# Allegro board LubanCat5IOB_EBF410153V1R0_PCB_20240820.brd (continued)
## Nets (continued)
N16593791: R12.2 R13.1 R17.1 U2.11(FB)
N16594273: J5.1 J5.5 L1.1
N16594503: C26.1 R9.2 R16.1 U2.12(EN)
N16594633: R15.2 U2.3(PG)
N16594645: R14.2 R18.1 U2.6(MODE)
N16594663: C25.1 R14.1 R15.1 U2.9(VCC)
N16594691: R8.1 U2.8(BST)
N16605614: C36.1 J6.15(SH) J6.16(SH1) R42.1
N16605678: J6.13(YELC) R39.1
N16605786: R45.1 U4.32(LED0)
N16605856: C35.1 J6.1(CT)
N16606070: J6.12(GRLC) R40.1
N16606404: L4.1 U4.30(REG_OUT)
N16606548: R25.1 U4.39(RSET)
N16607242: R23.2 U4.25(RXD0)
N16607246: R24.2 U4.24(RXD1)
N16607250: R26.2 U4.23(RXD2)
N16607260: R27.2 U4.22(RXD3)
N16607264: R28.2 U4.27(RXC)
N16607268: R29.2 U4.26(RXCTL)
N16607434: C33.1 R384.1 Y1.1
N16607930: R35.2 U4.31(INTB)
N16608272: C34.1 R385.2 U4.36(XTAL_IN) Y1.3
N16611232: C58.1 D7.2 R69.2 R70.2 U3.12(PHYRSTB)
N16611438: C57.1 J7.15(SH) J7.16(SH1) R71.1
N16611542: R74.1 U3.32(LED0)
N16611608: C56.1 J7.1(CT)
N16612146: L7.1 U3.30(REG_OUT)
N16612282: R53.1 U3.39(RSET)
N16612988: R51.2 U3.25(RXD0)
N16612992: R52.2 U3.24(RXD1)
N16612996: R54.2 U3.23(RXD2)
N16613006: R55.2 U3.22(RXD3)
N16613010: R56.2 U3.27(RXC)
N16613014: R57.2 U3.26(RXCTL)
N16613204: C54.1 R387.1 Y2.1
N16613212: C55.1 R386.2 U3.36(XTAL_IN) Y2.3
N16613364: J7.11(GRLA) R64.1
N16613452: J7.13(YELC) R66.1
N16613812: R63.2 U3.31(INTB)
N16620498: R95.1 U6.3(ISET)
N16620622: C86.1 R93.2 U6.4(EN)
N16621700: J8.1(SH1) J8.2(SH2) J8.3(SH3) J8.4(SH4) L12.1
N16621974: R106.1 U14.15(DPU)
N16621978: R107.1 U14.14(DMU)
N16622106: J10.5(SH1) J10.6(SH2) J10.11(SH1) J10.12(SH2) L13.1
N16622154: C104.1 C105.1 R111.1 U15.2(VCC)
N16622302: R109.2 R110.2 U15.3(OUT)
N16622762: J9.19(SH1) J9.20(SH2) J9.21(SH1) J9.22(SH2) L11.1
N16624042: R103.1 U13.3(ISET)
N16624166: C99.1 R102.2 U13.4(EN)
N16624284: R99.1 U7.3(ISET)
N16624408: C89.1 R96.2 U7.4(EN)
N16625162: C102.1 U14.3(XOUT) Y3.1
N16625190: C103.1 U14.4(XIN) Y3.3
N16625358: R108.1 U14.13(REXT)
N16625468: C98.1 R101.1 U14.17(VBUSM)
N16625496: R105.1 U14.16(XRSTJ)
N16625548: R104.1 U14.18(BUSJ)
N16630017: R121.2 U16.26(CE)
N16630071: C106.1 C107.1 R112.1 U16.17(AVDD)
N16630361: C112.1 U16.24(LIN1)
N16630365: C113.1 U16.23(RIN1)
N16630441: C115.1 U16.22(LIN2)
N16630445: C117.1 U16.21(RIN2)
N16630545: C118.1 U16.20(VMID)
N16630549: C119.1 U16.19(ADCVREF)
N16630553: C120.1 U16.10(VREF)
N16778766: Q10.1(GATE) Q11.1(GATE) Q12.1(GATE) Q13.1(GATE) R169.2 R171.1
N16778768: Q12.3(DRAIN) R165.2 R166.2
N16778770: Q13.3(DRAIN) R167.2 R168.2
N16778784: J16.G1(20) J16.G2(21) J16.G3(22) J16.G4(23) R156.1
N16779726: Q8.1(GATE) Q9.3(DRAIN) R158.2
N16779736: Q9.1(GATE) R159.1 R160.1
N16779830: Q10.3(DRAIN) R161.2 R162.2
N16779838: Q11.3(DRAIN) R163.2 R164.2
N16779929: C142.1 Q7.1(GATE) R153.2
N16781420: Q19.1(GATE) Q20.1(GATE) Q21.1(GATE) Q22.1(GATE) R190.2 R192.1
N16781422: Q21.3(DRAIN) R186.2 R187.2
N16781424: Q22.3(DRAIN) R188.2 R189.2
N16781438: J17.G1(20) J17.G2(21) J17.G3(22) J17.G4(23) R177.1
N16782370: Q17.1(GATE) Q18.3(DRAIN) R179.2
N16782390: Q18.1(GATE) R180.1 R181.1
N16782474: Q19.3(DRAIN) R182.2 R183.2
N16782482: Q20.3(DRAIN) R184.2 R185.2
N16782583: C154.1 Q16.1(GATE) R174.2
N16783799: J18.G1(20) J18.G2(21) J18.G3(22) J18.G4(23) R195.1
N16783872: D40.1 R197.1 R200.1
N16786078: D46.1 R209.1
N16791174: Q28.1(BASE) R211.1 R212.2
N16794123: Q27.1(GATE) R213.2 R215.1
N16794280: Q27.3(DRAIN) R214.1
N16795019: C316.1 Q29.1(BASE) R193.2 R194.1
N16796110: Q28.3(COLLECTOR) R215.2
N16803397: C156.1 U25.6(BOOT)
N16803401: C156.2 L16.1 U25.2(SW)
N16803409: C157.1 R218.1 R227.1 U25.4(FB)
N16803499: R221.1 R222.1 U25.5(EN)
N16803635: C164.1 U26.5(X1) Y4.1
N16803642: R234.1 U26.10(IREF)
N16803673: C166.1 C167.1 R235.2 U26.15(VDDODA)
N16803735: R216.1 U26.20(CLK0P)
N16803772: R217.1 U26.19(CLK0N)
N16803867: R228.1 U26.18(CLK1P)
N16803869: R229.1 U26.17(CLK1N)
N16803965: C165.1 R230.1 Y4.3
N16804075: R230.2 U26.6(X2)
N16804652: J19.38(DEVSLP) R237.1
N16804754: J19.10(DAS/DSS) R236.1
N16810459: R238.1 U26.14(CLK2P)
N16810480: R239.1 U26.13(CLK2N)
N16810864: R242.1 U26.12(CLK3P)
N16810873: R243.1 U26.11(CLK3N)
N16814949: C188.1 U27.4(NC)
N16815530: R246.1 U27.3(EN)
N16823880: J20.B11(WAKE#) R247.2
N16823920: J20.B12(RSVD_B12) R248.2
N16831021: Q30.1(GATE) Q31.3(COLLECTOR) R255.2
N16831025: Q31.1(BASE) R256.2 R257.1
N16835418: C194.1 R249.1 R250.1 U28.4(FB)
N16835425: C179.2 L17.1 U28.2(SW)
N16835491: C179.1 U28.6(BOOT)
N16835549: R251.1 R252.1 U28.5(EN)
N16843509: C199.1 L18.1 U29.2(SW)
N16843563: R262.2 R263.1 U29.5(EN)
N16843694: C209.1 J21.2(RST) R258.2 U30.4
N16843698: C208.1 J21.3(CLK) R259.2 U30.5
N16843753: C200.2 R254.2 R261.1 U29.4(FB)
N16843960: J23.1(MIC-P) R264.2 R265.2
N16843974: J23.7(SPK-N) R266.2
N16843993: C199.2 U29.6(BOOT)
N16844137: J23.20(W-DISABLE) R267.1
N16844170: C207.1 J21.7(I/O) R253.2 R260.2 U30.1
N16844211: J23.22(PERST1) R268.1
N16844471: J23.38(USB-D+) R270.1
N16844509: J23.36(USB-D-) R269.1
N16890924: R65.1 U31.5(EN)
N16890968: C224.1 U31.6(BOOT)
N16890980: C224.2 L20.1 U31.2(SW)
N16890990: C225.1 R36.1 R271.1 U31.4(FB)
N16891594: R6.1 U1.5(EN)
N16891638: C6.1 U1.6(BOOT)
N16891644: C6.2 L2.1 U1.2(SW)
N16891660: C7.1 R4.1 R7.1 U1.4(FB)
N16892291: C14.2 L21.1 U32.2(SW)
N16892293: C232.1 R272.1 R274.1 U32.4(FB)
N16892339: C14.1 U32.6(BOOT)
N16892349: C239.1 R273.1 U32.5(EN)
N16906360: C241.1 U35.2(OSCO) Y5.2
N16906384: C240.1 U35.1(OSCI) Y5.1
N16906410: R276.2 R277.1 U35.7(CLKOUT)
N16921467: D58.1 R287.2
N16921931: D60.1 R293.2
N16922864: C247.1 U38.3(C1-)
N16922866: C247.2 U38.1(C1+)
N16922868: C248.1 U38.5(C2-)
N16922870: C248.2 U38.4(C2+)
N16922872: C246.1 U38.6(V-)
N16922874: C245.1 U38.2(V+)
N16935603: C128.1 R138.1 R141.1 U17.4(FB)
N16935613: C127.2 L25.1 U17.2(SW)
N16935675: C127.1 U17.6(BOOT)
N16935717: R139.1 R140.1 U17.5(EN)
N16966626: C259.1 C262.1 R306.2 U39.4(EN) U40.4(EN)
N16966707: C258.1 C265.1 R305.2 U18.4(EN) U41.4(EN)
N16966725: R307.1 U18.3(ISET)
N16966842: R310.1 U41.3(ISET)
N16967089: R308.1 U39.3(ISET)
N16967190: R309.1 U40.3(ISET)
N17015969: R323.1 U48.3(ISET)
N17016021: C284.1 R324.2 U48.4(EN)
N17044511: J13.55(PEWAKE0#) R147.2 R148.2
N17044551: J13.53(CLKREQ0#) R145.2
N17044654: J13.52(PERST0#) R144.1
N17044656: J13.56(W_DISABLE1#) R146.1
N17044766: J13.3(USB_D+) R142.2
N17044768: J13.5(USB_D-) R143.2
N17083881: Q5.1(GATE) Q32.3(COLLECTOR) R319.2
N17083895: Q32.1(BASE) R320.2 R321.1
N17085595: C290.1 R316.1 R322.1 U43.4(FB)
N17085599: C283.2 L26.1 U43.2(SW)
N17085653: C283.1 U43.6(BOOT)
N17085706: R317.1 R318.1 U43.5(EN)
N17139366: Q1.1(GATE) Q2.3(COLLECTOR) R132.2
N17139370: Q2.1(BASE) R133.2 R135.1
N17139392: D15.1(K) J12.1 R129.2
N17139440: Q1.2(SOURCE) R127.2 R131.2 R132.1
N17139454: Q1.3(DRAIN) R129.1
N17140097: C126.1 D83.2 P1.1(OUT) R126.2 R130.1
N17140111: C126.2 D78.2 P1.2(GND) R134.1 R136.1
N17140177: C125.1 R125.2 R126.1
N17141731: C210.1 C211.1 C218.1 C219.1 C278.1 R341.2 R342.2 U42.6(VDD)
N17141824: C303.1 C304.1 C305.1 C306.1 C307.1 R347.2 R348.2 U46.6(VDD)
N17141906: R345.2 R346.1 U42.1(CTRL)
N17141982: R343.2 U42.4(INN)
N17142014: C279.2 R343.1
N17142016: R344.2 U42.3(INP)
N17142030: C299.2 R344.1
N17142049: L19.1 U42.5(VON)
N17142051: L27.1 U42.8(VOP)
N17142055: C302.1 U42.2(BYPASS)
N17142188: R351.2 R352.1 U46.1(CTRL)
N17142262: R349.2 U46.4(INN)
N17142284: R350.2 U46.3(INP)
N17142286: C308.2 R349.1
N17142298: C309.2 R350.1
N17142317: L28.1 U46.5(VON)
N17142331: L29.1 U46.8(VOP)
N17142348: C312.1 U46.2(BYPASS)
N17143919: C288.1 D81.2 J11.6 R119.2 R120.1
N17143960: J11.2 R327.1
N17143962: C116.1 D82.2 J11.1 R114.1 R115.2 R116.1
N17143973: C111.1 R113.1 R115.1
N17144006: D79.2 J11.4 Q3.2(SOURCE)
N17144062: C289.1 Q3.1(GATE) Q4.1(GATE) R326.1
N17144068: C287.2 R124.2
N17144070: C122.2 R122.2
N17144072: Q3.3(DRAIN) R122.1 R123.1
N17144086: Q4.3(DRAIN) R124.1 R325.1
N17144157: D80.2 J11.3 Q4.2(SOURCE)
N17145436: D25.1 J41.2 R338.2
N17145440: D47.1 J41.3 R339.2
N17145452: D48.1 J41.4 R340.2
N17149601: LED1.2(ANODE) R11.2
N17201409: R353.2 U44.21(A0)
N17255856: D49.1 R354.1
N17266822: Q35.1(BASE) R334.2 R335.1
N17266886: LED2.2(ANODE) R128.2
N17266888: LED2.1(CATHODE) Q35.3(COLLECTOR)
N17604055: R384.2 R385.1 U4.37(XTAL_OUT)
N17605387: R386.1 R387.2 U3.37(XTAL_OUT)

Pads without a net: J1 30; J2 14 16; J4 4 6 16 22 24 26 28 52; J9 14 15 17 18; J11 7 8; J13 6 8 9 10 11 12 13 14 15 16 17 19 20 21 22 23 32 34 36 38 40 42 44 46 48 50 54 58 59 60 61 62 64 65 66 67 68 70 71 73; J14 14; J15 14; J18 14; J19 5 6 7 8 11 13 17 19 20 22 23 24 25 26 28 30 32 34 36 40 42 44 46 48 56 58 67 68 69; J20 A5 A6 A7 A8 A19 A25 A26 A29 A30 A32 B5 B6 B9 B23 B24 B27 B28 B30; J21 4 6; J23 3 5 6 16 17 19 28 30 32 42 44 45 46 47 48 49 51; J28 1; J29 1; J32 13 14; J33 13 14; J34 13 14 16 17 19 20; J35 13 14 16 17 19 20; J36 13 14 16 17 19 20; J37 13 14 16 17 19 20; NOREF 1; NOREF#2 1; NOREF#3 1; NOREF#5 1; NOREF#7 1; NOREF#9 1; NOREF#10 1; NOREF#11 1; NOREF#12 1; NOREF#13 1; NOREF#14 1; NOREF#15 1; NOREF#16 1; NOREF#17 1; NOREF#18 1; NOREF#19 1; U2 4; U14 2 19 21 22 23 24; U16 9 25; U30 3; U44 1

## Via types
v1: diameter 0.406, hole 0.203, TOP to BOTTOM, 2357 vias
v2: diameter 0.356, hole 0.203, TOP to BOTTOM, 308 vias
v3: diameter 0.508, hole 0.254, TOP to BOTTOM, 4 vias

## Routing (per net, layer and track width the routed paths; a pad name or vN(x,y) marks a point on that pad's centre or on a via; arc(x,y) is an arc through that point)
1V05_AVDD_PHY0: length 18.4
  TOP w0.203: U4.3 v1(71.46,81.04) ; v1(74.47,79.22) 74.11,78.87 U4.38 ; U4.8 v1(69.46,81.04)
  TOP w0.254: R47.2 v1(77.47,75.33) C42.1
  ART04 w0.381: v1(69.46,81.04) v1(71.46,81.04) 71.88,80.62 71.88,79.6 72.26,79.22 v1(74.47,79.22) 77.13,79.22 77.47,78.88 v1(77.47,75.33)
  BOTTOM w0.254: C41.1 73.75,78.5 v1(74.47,79.22)
1V05_AVDD_PHY1: length 20.5
  TOP w0.203: U3.8 v1(51.06,81.04) ; v1(56.07,79.1) 55.94,79.1 55.71,78.87 U3.38 ; U3.3 v1(53.06,81.04)
  TOP w0.254: C65.1 v1(58.67,75.33) R76.2
  ART04 w0.381: 55.3,79.22 54.94,78.87 54.94,75.83 56.03,74.74 56.64,74.74 57.23,75.33 v1(58.67,75.33) ; 55.3,79.22 54.94,79.58 54.94,80.51 54.41,81.04 v1(53.06,81.04) ; 55.3,79.22 55.94,79.22 v1(56.07,79.1)
  BOTTOM w0.254: v1(51.06,81.04) 51.42,80.68 C62.1 C63.1 53.2,80.9 v1(53.06,81.04) ; C64.1 55.82,79.1 v1(56.07,79.1)
1V05_DVDD_PHY0: length 11.1
  TOP w0.203: U4.21 68.66,74.64 v1(68.53,74.51)
  TOP w0.254: R46.1 v1(76.45,75.33) C39.1
  ART04 w0.381: v1(76.45,75.33) 76.2,75.07 72.9,75.07 72.64,75.33 69.35,75.33 v1(68.53,74.51)
  BOTTOM w0.381: C38.1 68.55,74.54 v1(68.53,74.51)
1V05_DVDD_PHY1: length 20.9
  TOP w0.203: U3.21 50.26,74.74 v1(50.08,74.56)
  TOP w0.254: R75.1 v1(59.69,75.33) C60.1
  ART04 w0.381: v1(50.08,74.56) 51.18,74.56 52.83,72.91 57.4,72.91 58.17,73.67 61.98,73.67 62.48,74.18 62.48,75.45 61.98,75.96 60.33,75.96 v1(59.69,75.33)
  BOTTOM w0.381: v1(50.08,74.56) 50.15,74.64 C61.1
1V8_DVDD_PHY1: length 33
  TOP w0.178: v1(53.11,74.54) 53.06,74.59 U3.28
  TOP w0.254: R381.1 C59.1 v1(61.6,75.32)
  ART04 w0.381: v1(53.11,74.54) 53.95,73.7 56.54,73.7 57.28,74.44 60.72,74.44 v1(61.6,75.32)
  BOTTOM w0.254: v1(53.11,74.54) 52.91,74.34 50.9,74.34 50.42,73.85 R48.1 R49.1 ; R70.1 44.71,79.52 R62.1 R61.1 46.4,81.22 47.52,81.22 48.01,80.73 48.01,78.81 49.43,77.38 49.43,72.93 R49.1 ; R49.1 R50.1
  BOTTOM w0.381: v1(53.11,74.54) 53.2,74.63 C51.1 C50.1
3V3_AVDD_PHY0: length 18.6
  TOP w0.203: U4.40 73.26,79.67 73.47,79.87 v1(73.47,81.11) ; v1(66.92,80.37) 67.62,79.67 U4.11
  TOP w0.254: v1(73.47,81.11) 73.47,81.68 73.98,82.18 C45.1
  TOP w0.305: R364.1 77.25,82.79 75.92,82.79 75.45,82.32 C45.1
  BOTTOM w0.254: v1(66.92,80.37) 67.09,80.53 C46.1 67.67,81.8 68.18,82.31 72.96,82.31 73.47,81.8 v1(73.47,81.11) 73.63,80.95 C44.1
3V3_AVDD_PHY1: length 17.2
  TOP w0.203: v1(49.56,81.04) U3.11 ; v1(55.07,81.11) 55.07,79.87 54.86,79.67 U3.40
  TOP w0.254: R383.1 60.2,82.18 59.56,82.82 58.3,82.82 C67.1 55.58,82.18 55.07,81.68 v1(55.07,81.11)
  BOTTOM w0.254: C66.1 49.27,80.76 v1(49.56,81.04) 49.56,81.29 50.09,81.83 54.35,81.83 v1(55.07,81.11) 55.23,80.95 C68.1
3V3_DVDD_PHY0: length 34.4
  TOP w0.203: U4.28 71.46,74.94 71.68,74.72 ; U4.29 71.86,74.9 71.68,74.72 ; 71.68,74.72 v1(71.68,74.51)
  TOP w0.381: R363.1 79.5,73.67 C47.1 C49.1 v1(79.49,75.28) C48.1
  ART04 w0.381: v1(71.68,74.51) 72.26,73.93 78.11,73.93 79.45,75.28 v1(79.49,75.28)
  BOTTOM w0.254: R22.1 R21.1 ; R21.1 67.94,73.67 67.69,73.93 R41.1 66.3,78.88 64.78,78.88 R34.1 R33.1 ; R21.1 R20.1 69.09,73.8 69.34,74.06 71.22,74.06 v1(71.68,74.51)
  BOTTOM w0.381: C30.1 C29.1 ; C29.1 71.6,74.59 v1(71.68,74.51) ; C29.1 71.61,75.07 R35.1 R45.2
3V3_DVDD_PHY1: length 35.2
  TOP w0.203: 53.7,74.72 53.46,74.95 U3.29
  TOP w0.254: 53.7,74.72 53.7,74.31 53.34,73.95 v1(53.34,73.47) C69.1
  BOTTOM w0.254: R73.2 54.87,77.87 55.75,77.87 56.9,79.01 ; R69.1 42.55,82.91 43.06,83.42 56.3,83.42 56.9,82.82 56.9,79.01 ; 56.9,79.01 57.19,78.72 R64.2
  BOTTOM w0.305: C70.1 54.23,73.79 C71.1 R382.1 ; C70.1 R63.1 R74.2 R73.2 ; C70.1 53.67,73.8 v1(53.34,73.47)
GND: length 2977.3
  TOP w0.152: J4.14 v2(70.44,67.76) ; J2.52 v2(78.04,19.73) ; J4.40 v2(75.64,67.76) ; J3.18 45.67,67.32 v2(45.27,66.92) ; J2.27 v2(73.24,22.61) ; v2(46.87,66.92) 47.27,67.32 J3.26 ; v2(43.67,20.51) J1.7 v2(43.67,22.44) ; J4.83 v2(84.44,64.36) ; v2(86.84,63.52) 87.24,63.92 J4.97 ; J4.67 v2(81.24,64.36) ; v2(43.67,66.92) 44.07,67.32 J3.10 ; J2.17 v2(71.24,22.61) ; J2.76 82.84,17.45 82.44,17.05 v2(82.44,16.85) ; v2(68.04,22.61) J2.1 ; J2.51 v2(78.04,22.61) ; J1.48 v2(51.67,17.85) ; J2.33 v2(74.44,22.61) ; J2.18 71.24,19.54 v2(71.58,19.88) ; v2(82.84,66.92) 83.24,67.32 J4.78 ; J1.51 v2(52.47,22.44) ; v2(84.04,17.69) J2.82 ; J1.102 v2(42,17.86) ; J2.12 v2(70.04,19.96) ; v2(70.04,22.61) J2.11 ; J1.54 v2(52.87,17.69) ; J4.99 v2(87.64,64.36) ; J2.58 v2(79.24,17.69) ; J1.101 v2(42,20.51) ; J4.8 v2(69.24,67.76) ; J4.20 v2(71.64,67.76)
  TOP w0.173: C9.2 v1(151.51,14.75)
  TOP w0.203: J3.43 v2(50.87,64.4) ; 61.23,34.69 56.26,34.69 55.27,33.7 J1.65 55.27,20.66 v2(55.07,20.46) ; 54.87,17.58 J1.64 54.87,20.26 v2(55.07,20.46) ; J1.29 48.07,19.89 v2(48.13,19.83) ; v2(59.69,66.94) 59.67,66.96 J3.88 ; J2.34 74.44,17.69 v2(74.42,17.67) ; 58.17,69.79 58.17,69.38 58.47,69.08 J3.82 58.47,68.03 v2(58.8,67.71) ; U16.13 21.35,74.81 v1(21.34,74.82) ; C316.2 119.01,84.34 ; J4.2 68.04,68.16 v2(67.64,67.76) ; v2(49.27,66.92) 49.67,67.32 J3.38 ; J2.91 v2(86.04,22.61) ; J2.28 73.24,19.58 v2(73.51,19.85) ; v2(57.67,16.85) 58.22,16.85 58.47,17.11 J1.82 J1.81 58.47,30.29 58.88,30.7 61.22,30.7 v1(61.23,30.69) ; v1(20.32,75.71) U16.4 ; v2(44.47,22.44) 44.87,22.84 46.51,22.84 46.87,22.48 J1.23 ; J2.104 v2(88.12,17.69) ; v2(88.12,22.61) J2.103 ; v2(83.64,22.61) J2.79 ; J4.96 86.84,67.96 87.04,67.76 v2(87.24,67.76) J4.98 ; J3.37 v2(49.67,64.4) ; 76.38,17.82 76.44,17.88 J2.44 ; J3.54 52.87,67.32 v2(52.47,66.92) ; J4.19 v1(71.64,64.4) ; v2(62.13,69.23) 62.07,69.17 J3.100 ; J1.100 v2(62.07,17.69) ; J3.53 v2(52.87,64.4) ; J4.49 v1(77.64,65.77) ; R136.2 v1(4.95,86.88) ; v1(74.37,70.7) 73.64,69.97 J4.30 ; J3.62 54.47,68.99 54.23,69.23 54.23,69.74 ; v2(55.07,20.46) 55.67,19.86 J1.68 ; J4.68 v2(81.24,67.76) ; J4.84 v2(84.44,69.22) ; v2(45.64,64.18) 45.67,64.2 J3.17 ; 56.08,69.74 56.08,69.41 56.47,69.02 J3.72 56.47,67.91 56.68,67.71 v2(56.9,67.71) ; v2(51.94,19.83) 51.67,19.56 J1.48 ; J3.27 47.67,64.28 v2(47.78,64.18) ; U16.18 v1(21.34,75.71) ; J3.11 44.47,64.2 v2(44.48,64.2) ; J1.99 v2(62.07,22.61) ; J3.99 v1(62.07,64.4) ; J4.90 v2(85.64,69.22) ; J3.94 60.87,69.22 v2(60.88,69.23) ; J4.100 87.64,67.32 v2(87.24,66.92) ; J2.57 v2(79.24,22.61) ; v2(49.66,17.87) 49.67,17.89 J1.38 49.67,19.46 v2(50.04,19.83) ; J4.43 v1(76.44,64.4) ; J3.75 v2(57.27,64.4) ; J3.32 v2(48.47,67.76) ; J2.73 v2(82.44,22.61) ; J2.2 v2(68.04,19.96) ; J1.32 v2(48.47,17.69)
  TOP w0.254: J4.1 v1(68.04,64.4) 67.77,64.13 67.77,54.83 arc(67.88,54.23) 68.22,53.73 arc(68.67,53.43) 69.19,53.33 75.81,53.33 v1(75.82,53.32) 81.82,53.32 v1(82.55,52.59) 83.01,53.05 93.46,53.05 arc(94.18,53.19) 94.78,53.59 v1(95.15,53.96) 95.15,54.14 98.12,57.11 arc(98.43,57.32) 98.79,57.39 101.82,57.39 arc(102.67,57.56) 103.4,58.05 v1(104.39,59.04) 107.03,61.68 arc(107.5,62.39) 107.67,63.23 v1(107.67,63.95) 107.67,75.45 108.2,75.99 108.2,78.32 D73.1 v1(107.64,79.57) ; U2.10 17.78,31.3 v1(17.28,31.8) ; J23.27 v1(130.9,73.54) ; J23.43 v1(124.5,73.54) ; D70.1 D69.1 v1(103.12,79.57) 103.12,80.9 v1(103,81.02) ; R244.2 100.08,48.83 ; 121.02,49.33 Y4.2 121.76,48.39 ; C96.2 v1(142.38,74.93) ; R335.2 v1(152.92,96.14) ; U18.2 v1(24.21,63.72) ; v1(5.97,71.57) v1(4.97,71.57) ; J36.18 v1(167.11,38.06) ; D16.1 v1(154.05,16.02) ; D19.1 v1(154.05,19.83) ; C4.2 v1(28.57,15.89) ; D78.1 v1(4.94,89.81) ; C170.2 153.15,83.45 v1(153.15,84.22) ; v2(52.47,22.44) 52.47,23.38 ; v1(113.79,78.87) 113.79,76.3 v1(113.08,75.59) ; R194.2 v1(119.51,75.69) ; v1(153.15,81.42) 153.15,82.18 C171.2 ; v1(85.81,80.33) 85.5,80.02 D27.1 ; C169.2 v1(158.11,84.22) ; U44.3 134.99,51.33 v1(135.38,50.94) 135.64,51.2 U44.2 ; D79.1 43.13,94.38 v1(42.64,93.9) ; v1(117.62,81.34) 118.53,82.26 Q29.2 118.55,83.51 C316.2 ; J34.21 v1(164.77,53.96) ; v1(10.13,76.07) 8.97,76.07 8.47,75.57 J14.16 ; 77.74,77.4 Y1.2 v1(76.97,78.24) ; v2(42.29,27.63) 42.04,27.63 41.68,27.27 41.68,25.82 42.04,25.46 42.97,25.46 v2(42.98,25.47) 42.98,24.98 v2(43.71,24.25) 43.71,22.48 v2(43.67,22.44) ; J32.23 v1(166.99,70.35) ; J8.B1 v1(23.4,98.39) ; R78.1 v1(63.25,72.66) ; J19.57 v1(165.79,92.75) ; 29.21,92.8 U8.3 U8.8 29.21,94.97 v1(29.11,95.07) 28.65,95.53 J8.A1 ; J36.21 v1(167.14,36.56) ; v1(128.08,70.11) v1(126.58,70.11) v1(125.08,70.11) v1(123.58,70.11) 120.12,70.11 118.08,68.07 118.08,61.21 117.78,60.91 117.78,57.81 v1(117.37,57.39) 117.47,57.39 118.07,56.79 119.67,56.79 v1(120.33,57.46) 120.04,57.75 120.04,64.57 v1(119.96,64.65) ; v1(162.07,46.39) 162.18,46.5 C275.2 ; R352.2 v1(35.69,69.76) ; D72.1 D71.1 105.38,81 v1(105.41,81.02) ; J14.31 v1(4.31,64.02) ; R346.2 v1(24.38,69.76) ; D75.1 v1(100.71,15.13) ; D21.1 v1(154.05,23.76) ; C69.2 v1(53.34,71.01) ; J1.103 62.55,22.84 ; Y2.2 v1(59.19,78.24) ; C221.2 v1(132.08,58.55) ; C302.2 v1(25.65,69.76) ; D20.1 v1(154.05,22.49) ; J4.25 v1(72.84,64.4) v1(72.84,59.08) 73.69,58.23 arc(73.85,58.12) 74.05,58.08 89.18,58.08 arc(90.19,58.28) v1(91.05,58.85) 94.46,62.27 94.46,66.21 94.79,66.53 SS6.1 ; D2.1 v1(28.57,14.87) ; v1(140.58,73.53) v1(138.9,73.53) 137.9,73.53 137.83,73.46 v1(137.83,62.37) 137.83,56.23 137.08,55.48 136.11,55.48 127.52,55.48 126.36,56.64 126.36,58.2 125.7,58.85 125.7,60.71 125.7,60.72 v1(125.7,62.39) J23.40 ; C104.2 v1(162.43,96.14) ; J36.24 167.42,35.06 ; v1(99.11,51.42) 99.47,51.07 R245.2 ; C281.2 v1(19.66,20.7) ; J19.33 v1(159.79,92.75) ; 80.13,80.54 Y1.4 79.24,81.31 v1(79.12,81.42) ; D5.1 87.91,80.72 v1(88.21,81.02) ; D22.1 v1(154.05,25.03) ; v1(155.29,91.75) v1(155.29,92.75) J19.15 ; D68.1 D67.1 v1(100.88,79.57) 100.88,80.33 v1(101.6,81.04) ; v1(128.12,66.8) 128.1,66.78 J23.34 128.1,62.64 v1(127.85,62.39) ; R233.2 v1(118.36,44.96) 118.38,44.97 v1(119.52,44.97) Y4.4 ; LED1.1 v1(149.58,101.4) ; R234.2 v1(118.36,49.66) v1(119.36,49.66) v1(120.36,49.66) ; R108.2 v1(134.98,83.82) ; D54.1 D53.1 v1(94.15,79.57) 94.15,80.94 v1(94.23,81.02) ; 58.67,81.52 C67.2 v1(59.44,82.18) ; C223.2 v1(144.91,59.32) ; U26.9 115.14,49.03 v1(115.44,48.73) 115.78,48.39 C165.2 ; C39.2 v1(76.95,76.84) C42.2 v1(78.51,76.84) ; v1(37.08,69.75) 37.08,69.76 36.96,69.89 C312.2 ; J44.6 32.47,14.8 v1(32.57,14.89) v1(32.57,15.89) ; C271.2 v1(162.2,63.9) ; U2.2 v1(15.39,28.22) ; D30.1 87.19,80.08 v1(86.94,80.33) ; v1(167.11,62.46) J34.4 v1(164.77,62.46) ; J23.26 v1(131.3,62.39) ; C15.2 v1(17.41,16.52) ; v1(121.47,33.68) 121.12,33.33 U35.4 ; J19.45 v1(162.79,92.75) ; 22.61,94.91 U9.8 U9.3 22.61,92.78 ; v1(32.54,73.4) 32.56,73.42 C211.2 ; v1(138.69,69.21) 139.28,68.62 140.72,68.62 v1(141.3,69.2) ; v1(89.92,81.02) 89.61,80.72 v1(89.61,79.57) D14.1 D50.1 ; C183.2 v1(156.08,81.43) ; v1(1.91,91.38) 1.91,91.37 D83.1 ; v1(79.88,47.64) 79.96,47.56 94.41,47.56 99.16,52.31 105.23,52.31 115.34,62.42 v1(116.59,62.42) 117.09,62.93 117.09,70.53 J23.53 ; v1(40.67,63.74) 39.78,63.74 R337.2 ; C60.2 v1(60.44,76.84) ; v1(32.2,90.23) 31.75,90.69 D80.1 ; U5.8 20.44,85.87 v1(19.94,86.37) ; D4.1 v1(17.41,14.24) ; J36.23 v1(167.11,35.56) ; U12.3 U12.8 v1(141.1,86.36) ; J23.4 v1(143.3,62.36) ; J23.37 v1(126.9,73.54) ; D62.2 v1(103.37,36.07) ; D18.1 v1(154.05,18.56) ; C54.2 56.27,80.91 v1(56.07,81.11) ; J19.73 v1(169.79,96.07) ; v1(8.08,69.69) 7.96,69.57 J14.28 v1(4.98,69.57) ; D63.2 v1(102.74,25.56) ; v1(8.31,71.11) 8.27,71.07 J14.25 5.86,71.07 ; v1(98.65,79.49) D37.1 D66.1 ; v1(79.96,44.59) 79.96,44.87 79.25,45.58 ; R292.2 v1(141.22,31.75) ; 153.79,92.09 v1(153.79,92.75) J19.9 ; v1(78.44,72.79) 78.31,72.66 C31.2 ; J19.51 v1(164.29,92.75) ; C164.2 v1(118.36,46.1) ; U24.3 v1(111.76,78.86) ; v1(27.48,94.25) 27.48,93.94 26.76,93.23 D8.1 ; C105.2 v1(163.58,96.14) ; J23.35 v1(127.7,73.54) ; U26.16 v1(106.86,46.43) ; v1(5.82,80.57) 5.82,80.57 J14.6 8.63,80.57 v1(9.13,80.07) 8.63,79.57 J14.8 ; v1(91.92,79.57) D51.1 D52.1 ; J19.21 v1(156.79,92.75) 156.79,91.91 ; v1(62.23,34.69) 61.23,34.69 ; C74.2 17.52,85.37 v1(17.91,85.37) ; C5.2 v1(19.69,14.24) ; v1(164.77,45.06) J36.4 v1(167.11,45.06) ; D17.1 v1(154.05,17.29) ; D76.1 v1(104.78,15.13) ; v1(157,19.34) 157.04,19.39 J24.6 v1(159.79,19.39) ; J32.18 164.77,72.85 ; v1(133.3,73.54) J23.21 133.3,70.36 133.55,70.11 v1(134.08,70.11) ; 164.87,52.96 J34.23 v1(167.11,52.96) ; C236.2 v1(6.22,17.67) ; C72.2 v1(18.42,89.67) ; v1(60.44,72.66) C52.2 C53.2 v1(60.44,71.64) ; C220.2 v1(121.78,59.32) ; 46.43,73.78 47.68,73.78 48.27,74.37 v1(48.57,74.37) ; J19.3 v1(152.29,92.75) ; C48.2 v1(78.49,75.32) C49.2 ; C10.2 v1(151.51,21.22) ; v1(164.77,79.85) J32.4 v1(167.11,79.85) ; v1(4.97,74.57) 5.46,74.07 J14.19 ; Q35.2 v1(157.16,97.79) ; J1.104 62.55,17.33 v2(62.07,16.85) ; v1(129.58,70.11) 130.1,70.63 J23.29 v1(130.1,73.54) ; U33.3 v1(8.39,21.09) ; U42.7 25.65,76.09 v1(26.29,75.45) ; C163.2 v1(118.36,43.81) ; J19.27 v1(158.29,92.75) v1(158.29,91.75) ; v1(134.24,62.36) 134.5,62.62 J23.18 ; J23.50 v1(121.7,62.39) ; U15.1 v1(164.21,100.84) ; J34.18 v1(167.11,55.46) ; C95.2 v1(139.33,77.97) ; J2.102 67.57,19.78 ; v1(96.41,79.57) D65.1 D34.1 ; v1(21.69,88.14) 21.45,88.38 C73.2 ; v1(96.75,44.6) 96.75,46.22 96.04,46.93 ; U24.8 v1(111.76,83.2) ; D74.1 v1(95.89,15.13) ; J19.76 v1(171.39,90.68) ; C309.1 v1(37.72,67.97) ; C33.2 74.67,80.91 v1(74.47,81.11) ; U15.4 v1(160.4,100.84) ; C238.2 v1(117.11,39.65) ; C28.2 v1(13.97,14.87) ; D77.1 v1(109.6,15.13) ; C235.2 4.21,17.17 v1(4.19,17.19) ; v1(116.04,85.6) v1(116.04,83.56) 115.7,83.22 115.7,81.39 v1(115.94,81.15) 115.82,81.15 U23.8 U23.3 ; Q31.2 v1(15.72,39.43) ; Q31.2 v1(16.55,40.26) ; Q31.2 v1(16.55,38.61) ; Q31.2 v1(17.37,39.43) ; D23.2 v1(154.05,21.21) ; v1(24.26,94.02) 24.35,94.02 D9.1 ; C237.2 v1(122.43,41.26) ; R296.2 v1(133.48,31.75) ; D3.1 v1(23.74,14.87) ; U47.8 v1(131.19,26.8) ; v1(90.32,44.69) 90.32,46.01 ; Y3.2 148.58,82.71 ; J19.39 v1(161.29,92.75) ; D64.2 v1(103.37,30.49) ; C59.2 v1(63.25,74.69) ; U44.12 v1(129.14,50.2) ; C32.2 v1(78.44,71.64) ; J32.21 v1(166.99,71.35) ; J34.24 164.67,52.46 ; D61.2 v1(103.37,33.28) ; v1(8.71,65.04) v1(8.71,67.32) 9.32,67.93 9.32,68.57 v1(9.45,68.7) 10.06,69.31 10.06,71.84 9.19,72.71 8.49,72.71 v1(8.28,72.51) 8.21,72.57 J14.22 ; Y3.4 147.08,78.4 ; C182.2 v1(155.07,81.43) ; J19.71 v1(169.29,92.75) ; J19.75 v1(170.29,92.75) ; Y2.4 62.14,80.54
  TOP w0.305: U36.5 v1(142.75,23.87) ; U38.15 v1(131.23,21.2) ; U45.2 v1(121.79,29.08) ; J14.7 v1(8.13,80.07) ; D81.1 43.56,101.92 ; C98.2 v1(134.98,78.36) ; U45.8 v1(123.06,26.8) ; U19.5 v1(135,26.67) ; U47.2 v1(129.92,29.08) ; U5.9 v1(21.97,86.37)
  TOP w0.381: J20.B21 4.37,37.15 ; J20.B21 2.91,37.15 ; J20.B21 3.64,36.42 ; 7.41,30.15 J20.A28 ; J20.A28 8.87,30.15 ; J20.A28 8.14,29.42 ; J20.A28 8.14,30.88 ; J27.5 130.02,14.13 ; J27.5 131.09,13.05 ; J27.5 130.02,11.97 ; 11.37,93.67 J5.2 ; J5.2 12.1,95.15 ; J5.2 12.83,93.67 ; J5.2 12.1,92.19 ; 119.37,89.45 J9.13 ; J9.13 120.1,90.18 ; J9.13 119.37,90.91 ; J9.13 118.64,90.18 ; J20.A23 6.87,35.15 ; J20.A23 6.14,35.88 ; J20.A23 6.14,34.42 ; J20.A23 5.41,35.15 ; 113.25,24.77 J28.4 ; J28.4 112.52,25.49 ; J28.4 113.98,25.49 ; 94.78,20.53 SS8.1 ; SS8.1 101.33,20.53 ; SS8.1 98.06,17.26 ; SS8.1 98.06,23.81 ; SS10.1 144.8,22.71 ; SS10.1 144.8,17.16 ; SS10.1 142.02,19.93 ; SS10.1 147.58,19.93 ; J20.B22 1.64,36.88 ; J20.B22 1.64,35.42 ; J20.B22 2.37,36.15 ; DN2.3 v1(124.8,16.6) ; 1.64,31.42 J20.B26 ; J20.B26 2.37,32.15 ; J20.B26 1.64,32.88 ; U46.7 36.96,79.38 C307.2 v1(37.09,80.24) v1(37.09,81.24) v1(37.09,82.24) 37.09,84.94 v1(37.52,85.36) ; 7.41,34.15 J20.A24 ; J20.A24 8.14,34.88 ; J20.A24 8.87,34.15 ; J20.A24 8.14,33.42 ; 1.64,25.42 J20.B32 ; J20.B32 1.64,26.88 ; J20.B32 2.37,26.15 ; 136.62,88.5 J10.4 ; J10.4 137.6,87.52 ; J10.4 137.6,89.48 ; J10.4 138.58,88.5 ; 137.6,90.52 J10.10 ; J10.10 138.58,91.5 ; J10.10 136.62,91.5 ; J10.10 137.6,92.48 ; 132.83,35.23 SS12.1 ; SS12.1 130.05,38.01 ; SS12.1 132.83,40.79 ; SS12.1 135.6,38.01 ; 157.76,10.46 SS11.1 164.32,10.46 ; J20.B29 3.64,29.88 ; J20.B29 3.64,28.42 ; J20.B29 2.91,29.15 ; J20.B29 4.37,29.15 ; SS9.1 122.53,21.86 DN1.3 ; SS9.1 123.38,19.93 ; SS9.1 120.6,17.16 ; SS9.1 117.82,19.93 ; SS9.1 120.6,22.71 ; J27.2 142.52,13.05 ; J27.2 141.45,11.97 ; J27.2 141.45,14.13 ; J5.3 18.13,93.67 ; J5.3 17.4,92.19 ; J5.3 17.4,95.15 ; J5.3 16.67,93.67 ; 9.48,8.71 SW4.3 ; SW4.3 8.6,9.59 ; SW4.3 10.35,9.59 ; SW4.3 9.48,10.47 ; J20.A27 6.14,31.88 ; J20.A27 5.41,31.15 ; J20.A27 6.14,30.42 ; J20.A27 6.87,31.15 ; J20.A31 6.14,27.88 ; J20.A31 5.41,27.15 ; J20.A31 6.87,27.15 ; J20.A31 6.14,26.42 ; J20.B25 3.64,33.88 ; J20.B25 2.91,33.15 ; J20.B25 3.64,32.42 ; J20.B25 4.37,33.15 ; C311.2 v1(40.25,83.34) 40.25,86.86 39.49,87.62 35.94,87.62 35.18,86.86 35.18,82.81 C310.2 ; 105.1,19.53 J29.4 ; J29.4 106.55,19.53 ; J29.4 105.83,20.26 ; J29.4 105.83,18.8 ; 111.4,41 J26.2 112.02,40.37 ; J9.4 120.1,93.38 ; J9.4 119.37,92.65 ; J9.4 118.64,93.38 ; 7.05,11.54 SW4.1 ; SW4.1 7.93,12.42 ; SW4.1 7.93,10.66 ; SW4.1 8.8,11.54 ; C301.2 v1(28.95,83.45) 28.56,83.84 28.56,86.96 27.88,87.64 24.41,87.64 23.77,87.01 23.77,83.62 v1(23.5,83.34) C300.2 ; U42.7 25.65,79.51 C278.2 25.79,80.36 v1(25.79,80.36) v1(25.79,81.36) v1(25.79,82.36) 25.79,85.04 v1(26.06,85.31)
  TOP w0.508: v1(138.9,73.53) J23.15 138.9,69.42 v1(138.69,69.21) ; J34.26 167.01,65.66 166.65,66.01 ; J34.26 168.64,64.02 ; J34.26 J32.25 167.18,68.15 ; 84.15,85.56 84.49,85.22 J16.17 ; v1(118.07,74.29) 118.05,74.27 J23.53 ; J19.77 v1(150.69,91.34) ; 168.64,46.72 J36.26 J34.25 ; J24.11 v1(170.1,14.89) ; J16.11 84.33,88.69 ; v1(160.96,29.52) 160.93,29.49 J24.13 ; v1(164.8,33.04) 165.12,33.36 J36.25 ; v1(0.78,61.32) v1(0.78,65.13) v1(0.78,68.94) v1(0.78,72.75) v1(0.78,76.56) v1(0.78,80.37) v1(0.78,84.18) v1(0.78,87.99) v1(0.78,91.8) v1(0.78,95.61) ; J24.10 v1(160.5,14.89) ; 147.35,73.66 J23.54 149.4,71.48 ; J23.9 v1(141.3,69.2) ; J24.12 v1(168.6,28.88) ; J14.32 v1(2.67,85.22) ; J16.5 84.34,92.15 ; J32.26 v1(168.64,81.8)
  GND02 w0.381: J39.1 85.08,9.75 ; J39.1 84.35,10.48 ; J39.1 84.35,9.02 ; J39.1 83.63,9.75 ; 6.14,34.42 J20.A23 ; J20.A23 5.41,35.15 ; J20.A23 6.14,35.88 ; J20.A23 6.87,35.15 ; J20.A12 8.14,46.88 ; J20.A12 8.87,46.15 ; J20.A12 8.14,45.42 ; J20.A12 7.41,46.15 ; J7.10 47.01,88.73 ; J7.10 47.99,87.75 ; J7.10 47.01,86.77 ; J7.10 46.03,87.75 ; J20.A18 8.14,40.88 ; J20.A18 8.87,40.15 ; J20.A18 8.14,39.42 ; J20.A18 7.41,40.15 ; J39.S2 87.02,11.48 ; J39.S2 87.02,9.02 ; J39.S2 88.25,10.25 ; J39.S2 85.8,10.25 ; SW3.3 15.32,10.47 ; SW3.3 14.44,9.59 ; SW3.3 15.32,8.71 ; SW3.3 16.2,9.59 ; SS11.1 163.82,10.46 ; SS11.1 158.26,10.46 ; SS11.1 161.04,13.24 ; 111.4,41 J26.2 ; J26.2 112.02,41.62 ; J26.2 112.02,40.37 ; 36.47,9.97 J44.4 ; J44.4 37.2,10.7 ; J44.4 36.47,11.43 ; J44.4 35.75,10.7 ; SS5.1 32.06,69.31 ; SS5.1 34.83,66.53 ; SS5.1 29.28,66.53 ; SS5.1 32.06,63.75 ; 119.37,92.65 J9.4 ; J9.4 119.37,94.11 ; J9.4 120.1,93.38 ; J9.4 118.64,93.38 ; J20.A4 8.87,56.15 ; J20.A4 8.14,55.42 ; J20.A4 8.14,56.88 ; J20.A4 7.41,56.15 ; SS9.1 120.6,22.71 ; SS9.1 123.38,19.93 ; SS9.1 120.6,17.16 ; SS9.1 117.82,19.93 ; 8.14,29.42 J20.A28 ; J20.A28 8.14,30.88 ; J20.A28 8.87,30.15 ; J20.A28 7.41,30.15 ; J16.2 86.86,93.9 ; J16.2 86.29,94.47 ; J16.2 85.71,93.9 ; 140.37,13.05 J27.2 ; J27.2 141.45,11.97 ; J27.2 141.45,14.13 ; J27.2 142.52,13.05 ; 128.94,13.05 J27.5 ; J27.5 131.09,13.05 ; J27.5 130.02,11.97 ; J27.5 130.02,14.13 ; SS10.1 147.58,19.93 ; SS10.1 142.02,19.93 ; SS10.1 144.8,22.71 ; SS10.1 144.8,17.16 ; 76.01,9.75 J39.7 ; J39.7 77.46,9.75 ; J39.7 76.73,10.48 ; J39.7 76.73,9.02 ; 13.77,10.66 SW3.1 ; SW3.1 12.89,11.54 ; SW3.1 14.65,11.54 ; SW3.1 13.77,12.42 ; 137.6,87.52 J10.4 ; J10.4 137.6,89.48 ; J10.4 138.58,88.5 ; J10.4 136.62,88.5 ; J9.16 122.87,89.41 ; J9.16 122.87,87.95 ; J9.16 123.6,88.68 ; J9.16 122.14,88.68 ; 7.05,11.54 SW4.1 ; SW4.1 8.8,11.54 ; SW4.1 7.93,12.42 ; SW4.1 7.93,10.66 ; J20.B26 2.37,32.15 ; J20.B26 1.64,32.88 ; J20.B26 0.91,32.15 ; J20.B26 1.64,31.42 ; 5.41,43.15 J20.A15 ; J20.A15 6.14,42.42 ; J20.A15 6.87,43.15 ; J20.A15 6.14,43.88 ; 112.52,25.49 J28.4 ; J28.4 113.25,26.22 ; J28.4 113.25,24.77 ; J28.4 113.98,25.49 ; J12.2 107.18,41.5 ; J12.2 107.18,40.09 ; J12.2 106.47,40.8 ; J12.2 107.88,40.8 ; SW1.1 25.45,12.42 ; SW1.1 25.45,10.66 ; SW1.1 24.58,11.54 ; SW1.1 26.33,11.54 ; 40.47,9.97 J44.2 ; J44.2 39.75,10.7 ; J44.2 40.47,11.43 ; J44.2 41.2,10.7 ; J20.A27 6.87,31.15 ; J20.A27 5.41,31.15 ; J20.A27 6.14,30.42 ; J20.A27 6.14,31.88 ; 105.1,19.53 J29.4 ; J29.4 106.55,19.53 ; J29.4 105.83,18.8 ; J29.4 105.83,20.26 ; 0.91,36.15 J20.B22 ; J20.B22 2.37,36.15 ; J20.B22 1.64,35.42 ; J20.B22 1.64,36.88 ; J41.5 47.49,11.43 ; J41.5 46.76,10.7 ; J41.5 48.22,10.7 ; J41.5 47.49,9.97 ; 107.31,93.9 J18.2 ; J18.2 108.46,93.9 ; J18.2 107.89,94.47 ; 27,8.71 SW1.3 ; SW1.3 27.88,9.59 ; SW1.3 27,10.47 ; SW1.3 26.13,9.59 ; 0.91,40.15 J20.B18 ; J20.B18 1.64,40.88 ; J20.B18 2.37,40.15 ; J20.B18 1.64,39.42 ; J20.B29 3.64,29.88 ; J20.B29 3.64,28.42 ; J20.B29 4.37,29.15 ; J20.B29 2.91,29.15 ; 63.75,10.14 J38.2 ; J38.2 64.65,11.04 ; J38.2 62.84,11.04 ; J38.2 63.75,11.94 ; 85.86,85.22 J16.17 84.71,85.22 ; 85.71,90.43 J16.8 86.86,90.43 ; 3.64,36.42 J20.B21 ; J20.B21 2.91,37.15 ; J20.B21 3.64,37.88 ; J20.B21 4.37,37.15 ; 5.41,59.15 J20.A1 ; J20.A1 6.87,59.15 ; J20.A1 6.14,58.42 ; J20.A1 6.14,59.88 ; 29.28,20.53 SS7.1 ; SS7.1 32.06,17.76 ; SS7.1 34.83,20.53 ; SS7.1 32.06,23.31 ; 0.91,42.15 J20.B16 ; J20.B16 2.37,42.15 ; J20.B16 1.64,42.88 ; J20.B16 1.64,41.42 ; 65.38,11.04 J38.3 ; J38.3 66.29,10.14 ; J38.3 67.19,11.04 ; J38.3 66.29,11.94 ; SW2.1 19.61,12.42 ; SW2.1 19.61,10.66 ; SW2.1 20.49,11.54 ; SW2.1 18.73,11.54 ; 11.37,93.67 J5.2 ; J5.2 12.1,92.19 ; J5.2 12.1,95.15 ; J5.2 12.83,93.67 ; 20.28,9.59 SW2.3 ; SW2.3 21.16,8.71 ; SW2.3 22.04,9.59 ; SW2.3 21.16,10.47 ; 84.71,92.15 J16.5 85.86,92.15 ; 6.14,26.42 J20.A31 ; J20.A31 6.14,27.88 ; J20.A31 5.41,27.15 ; J20.A31 6.87,27.15 ; 0.82,15.18 J25.3 ; J25.3 1.8,16.15 ; J25.3 2.78,15.18 ; J25.3 1.8,14.2 ; 96.66,92.15 J17.5 95.51,92.15 ; 16.67,93.67 J5.3 ; J5.3 18.13,93.67 ; J5.3 17.4,92.19 ; J5.3 17.4,95.15 ; 95.51,85.22 J17.17 96.66,85.22 ; 31.75,10.7 J44.6 ; J44.6 33.2,10.7 ; J44.6 32.47,11.43 ; J44.6 32.47,9.97 ; 106.31,92.15 J18.5 107.46,92.15 ; J20.A24 8.87,34.15 ; J20.A24 7.41,34.15 ; J20.A24 8.14,33.42 ; J20.A24 8.14,34.88 ; J20.A20 8.87,38.15 ; J20.A20 7.41,38.15 ; J20.A20 8.14,38.88 ; J20.A20 8.14,37.42 ; J39.S1 74.06,11.48 ; J39.S1 75.29,10.25 ; J39.S1 74.06,9.02 ; J39.S1 72.84,10.25 ; J20.B4 1.64,56.88 ; J20.B4 1.64,55.42 ; J20.B4 0.91,56.15 ; J20.B4 2.37,56.15 ; 95.28,66.53 SS6.1 ; SS6.1 98.06,63.75 ; SS6.1 100.83,66.53 ; SS6.1 98.06,69.31 ; 3.64,44.42 J20.B13 ; J20.B13 3.64,45.88 ; J20.B13 4.37,45.15 ; J20.B13 2.91,45.15 ; 107.31,90.43 J18.8 108.46,90.43 ; 107.46,85.22 J18.17 106.31,85.22 ; J20.B25 4.37,33.15 ; J20.B25 2.91,33.15 ; J20.B25 3.64,33.88 ; J20.B25 3.64,32.42 ; J20.B7 4.37,53.15 ; J20.B7 3.64,52.42 ; J20.B7 3.64,53.88 ; J20.B7 2.91,53.15 ; 96.51,93.9 J17.2 ; J17.2 97.09,94.47 ; J17.2 97.66,93.9 ; SW4.3 10.35,9.59 ; SW4.3 9.48,8.71 ; SW4.3 9.48,10.47 ; SW4.3 8.6,9.59 ; 79.82,9.75 J39.4 ; J39.4 81.27,9.75 ; J39.4 80.54,9.02 ; J39.4 80.54,10.48 ; 65.41,86.77 J6.10 ; J6.10 65.41,88.73 ; J6.10 64.43,87.75 ; J6.10 66.39,87.75 ; 95.28,20.53 SS8.1 ; SS8.1 98.06,17.76 ; SS8.1 100.83,20.53 ; SS8.1 98.06,23.31 ; 137.6,90.52 J10.10 ; J10.10 138.58,91.5 ; J10.10 136.62,91.5 ; J10.10 137.6,92.48 ; 106.31,88.69 J18.11 107.46,88.69 ; 85.86,88.69 J16.11 84.71,88.69 ; J9.7 122.87,92.61 ; J9.7 122.14,91.88 ; J9.7 122.87,91.15 ; J9.7 123.6,91.88 ; 132.83,35.23 SS12.1 ; SS12.1 135.6,38.01 ; SS12.1 130.05,38.01 ; SS12.1 132.83,40.79 ; 96.66,88.69 J17.11 95.51,88.69 ; J20.B32 1.64,26.88 ; J20.B32 2.37,26.15 ; J20.B32 1.64,25.42 ; J20.B32 0.91,26.15 ; J9.13 120.1,90.18 ; J9.13 118.64,90.18 ; J9.13 119.37,89.45 ; J9.13 119.37,90.91 ; 96.51,90.43 J17.8 97.66,90.43
  ART03 w0.254: v1(21.34,75.71) v1(21.34,76.6) ; SS11.1 158.36,7.78 v1(155.52,7.78) v1(151.71,7.78) v1(147.9,7.78) v1(144.09,7.78) v1(140.28,7.78) v1(136.47,7.78) v1(132.66,7.78) v1(128.85,7.78) v1(125.04,7.78) v1(121.23,7.78) v1(117.42,7.78) v1(113.61,7.78) v1(109.8,7.78) v1(105.99,7.78) v1(102.18,7.78) v1(98.37,7.78) v1(94.56,7.78) v1(90.75,7.78) v1(86.94,7.78) v1(83.13,7.78) v1(79.32,7.78) v1(75.51,7.78) v1(71.7,7.78) v1(67.89,7.78) v1(64.08,7.78) v1(60.27,7.78) v1(56.46,7.78) v1(52.65,7.78) v1(48.84,7.78) v1(45.03,7.78) v1(41.22,7.78) v1(37.41,7.78) v1(33.6,7.78) v1(29.79,7.78) v1(25.98,7.78) v1(22.17,7.78) v1(18.36,7.78) v1(14.55,7.78) v1(10.74,7.78) ; v1(159.79,19.39) 159.79,21.47 v1(159.82,21.5) ; v1(129.09,102.22) 129.01,102.3 117.74,102.3 v1(117.66,102.22) v1(113.85,102.22) v1(112.85,102.22) v1(111.85,102.22) v1(110.04,102.22) v1(109.04,102.22) v1(106.23,102.22) v1(102.42,102.22) v1(98.61,102.22) v1(96.8,102.22) v1(95.8,102.22) v1(94.8,102.22) v1(93.8,102.22) v1(92.8,102.22) v1(91.8,102.22) v1(90.99,102.22) v1(87.18,102.22) v1(86.18,102.22) v1(85.18,102.22) v1(84.18,102.22) v1(83.18,102.22) v1(82.18,102.22) v1(81.18,102.22) v1(79.56,102.22) v1(78.46,102.22) v1(77.46,102.22) v1(76.46,102.22) v1(75.46,102.22) v1(74.46,102.22) v1(73.46,102.22) v1(72.46,102.22) v1(71.46,102.22) v1(70.46,102.22) v1(69.46,102.22) v1(68.46,102.22) v1(67.46,102.22) v1(66.46,102.22) v1(65.46,102.22) v1(64.46,102.22) v1(63.46,102.22) v1(62.46,102.22) v1(61.46,102.22) v1(60.46,102.22) v1(59.46,102.22) v1(58.46,102.22) v1(57.46,102.22) v1(56.46,102.22) v1(55.46,102.22) v1(54.46,102.22) v1(53.46,102.22) v1(52.46,102.22) v1(51.46,102.22) v1(50.46,102.22) v1(49.46,102.22) v1(48.46,102.22) v1(47.46,102.22) v1(46.46,102.22) v1(45.46,102.22) v1(44.46,102.22) v1(43.46,102.22) v1(42.46,102.22) v1(41.46,102.22) ; 165.54,83.6 v1(165.8,83.34) ; J28.4 110.57,25.49 ; 159,80.11 v1(159,80.42) ; v1(20.32,75.71) v1(20.32,76.6) 20.32,78.78 ; v1(62.23,34.69) 57.2,34.69 ; v1(154.05,80.43) v1(154.05,79.43) ; v1(155.05,80.43) v1(155.05,79.43) ; v1(154.05,19.83) v1(154.05,21.21) ; v1(66.64,44.59) 67,44.95 67.59,44.95 ; v1(15.58,50.27) v1(14.58,50.27) ; v1(26.56,40.61) v1(27.56,40.61) v1(28.56,40.61) ; v1(58.45,62.45) 59.16,62.45
  ART03 w0.381: SW4.1 7.93,12.42 ; SW4.1 7.05,11.54 ; SW4.1 8.8,11.54 ; SW4.1 7.93,10.66 ; 1.8,14.2 J25.3 ; J25.3 1.8,16.15 ; J25.3 0.82,15.18 ; J25.3 2.78,15.18 ; J9.4 119.37,94.11 ; J9.4 119.37,92.65 ; J9.4 120.1,93.38 ; J9.4 118.64,93.38 ; 137.6,90.52 J10.10 ; J10.10 138.58,91.5 ; J10.10 136.62,91.5 ; J10.10 137.6,92.48 ; 5.41,59.15 J20.A1 6.14,58.42 ; 118.64,90.18 J9.13 ; J9.13 119.37,89.45 ; J9.13 120.1,90.18 ; J9.13 119.37,90.91 ; 35.75,10.7 J44.4 ; J44.4 36.47,11.43 ; J44.4 36.47,9.97 ; J44.4 37.2,10.7 ; 0.91,26.15 J20.B32 ; J20.B32 2.37,26.15 ; J20.B32 1.64,25.42 ; J20.B32 1.64,26.88 ; SW3.3 16.2,9.59 ; SW3.3 14.44,9.59 ; SW3.3 15.32,8.71 ; SW3.3 15.32,10.47 ; SW2.1 19.61,12.42 ; SW2.1 20.49,11.54 ; SW2.1 19.61,10.66 ; SW4.3 9.48,10.47 ; SW4.3 9.48,8.71 ; SW4.3 10.35,9.59 ; SW4.3 8.6,9.59 ; SS7.1 34.83,20.53 ; SS7.1 29.28,20.53 ; SS7.1 32.06,23.31 ; 5.41,43.15 J20.A15 ; J20.A15 6.14,43.88 ; J20.A15 6.14,42.42 ; SS6.1 100.83,66.53 ; SS6.1 95.28,66.53 ; SS6.1 98.06,63.75 ; J44.6 32.47,11.43 ; J44.6 32.47,9.97 ; J44.6 31.75,10.7 ; J44.6 33.2,10.7 ; 12.1,92.19 J5.2 ; J5.2 11.37,93.67 ; J5.2 12.1,95.15 ; J5.2 12.83,93.67 ; 122.87,87.95 J9.16 ; J9.16 122.14,88.68 ; J9.16 122.87,89.41 ; J9.16 123.6,88.68 ; J9.7 123.6,91.88 ; J9.7 122.87,92.61 ; J9.7 122.14,91.88 ; J9.7 122.87,91.15 ; J5.3 18.13,93.67 ; J5.3 17.4,95.15 ; J5.3 17.4,92.19 ; J5.3 16.67,93.67 ; J20.A12 8.14,46.88 ; J20.A12 8.14,45.42 ; J20.A12 7.41,46.15 ; 40.47,9.97 J44.2 ; J44.2 40.47,11.43 ; J44.2 41.2,10.7 ; SS11.1 163.82,10.46 ; SS11.1 161.04,13.24 ; SS11.1 158.26,10.46 ; SW1.3 27,10.47 ; SW1.3 27.88,9.59 ; SW1.3 26.13,9.59 ; J10.4 137.6,89.48 ; J10.4 137.6,87.52 ; J10.4 136.62,88.5 ; J10.4 138.58,88.5 ; 20.28,9.59 SW2.3 ; SW2.3 22.04,9.59 ; SW2.3 21.16,10.47 ; J20.A31 6.87,27.15 ; J20.A31 5.41,27.15 ; J20.A31 6.14,26.42 ; 25.45,10.66 SW1.1 ; SW1.1 24.58,11.54 ; SW1.1 26.33,11.54 ; SW3.1 13.77,12.42 ; SW3.1 12.89,11.54 ; SW3.1 14.65,11.54 ; SW3.1 13.77,10.66
  ART04 w0.254: v1(166.74,86.77) 167.39,86.77 ; 161.11,76.67 v1(161.87,76.67) ; v1(22.17,7.78) v1(25.98,7.78) v1(29.79,7.78) v1(33.6,7.78) v1(37.41,7.78) v1(41.22,7.78) v1(45.03,7.78) v1(48.84,7.78) v1(52.65,7.78) v1(56.46,7.78) v1(60.27,7.78) v1(64.08,7.78) v1(67.89,7.78) v1(71.7,7.78) v1(75.51,7.78) v1(79.32,7.78) v1(83.13,7.78) v1(86.94,7.78) v1(90.75,7.78) v1(94.56,7.78) v1(98.37,7.78) v1(102.18,7.78) v1(105.99,7.78) v1(109.8,7.78) v1(113.61,7.78) v1(117.42,7.78) v1(121.23,7.78) v1(125.04,7.78) v1(128.85,7.78) v1(132.66,7.78) v1(136.47,7.78) v1(140.28,7.78) v1(144.09,7.78) v1(147.9,7.78) v1(151.71,7.78) v1(155.52,7.78) 158.36,7.78 SS11.1 164.41,10.46 ; v1(161.85,75.5) 161.11,75.5 ; v1(166.74,87.77) 167.39,87.77 ; J25.3 0.64,16.34 0.64,61.17 v1(0.78,61.32) v1(0.78,65.13) v1(0.78,68.94) v1(0.78,72.75) v1(0.78,76.56) v1(0.78,80.37) v1(0.78,84.18) v1(0.78,87.99) ; v1(161.93,74.42) 161.11,74.42 ; 60.35,59.78 v1(60.05,59.78) ; 105.18,15.13 v1(104.78,15.13) ; v1(129.09,102.22) v1(117.66,102.22) ; 141.1,95.9 v1(141.1,96.89) ; SS6.1 98.06,71.96 ; v1(166.74,88.77) 167.39,88.77 ; 167.39,89.77 v1(166.74,89.77) ; v1(143.1,96.89) 143.1,95.9 ; v1(142.1,96.89) 142.1,95.9 ; v1(166.74,84.77) 167.39,84.77 ; v1(166.74,85.77) 167.39,85.77 ; 136.96,69.92 v1(136.55,69.92)
  ART04 w0.381: J20.A18 8.87,40.15 ; J20.A18 8.14,40.88 ; J20.A18 8.14,39.42 ; J20.A18 7.41,40.15 ; 0.91,42.15 J20.B16 ; J20.B16 1.64,42.88 ; J20.B16 2.37,42.15 ; J20.B16 1.64,41.42 ; SS6.1 100.83,66.53 ; SS6.1 95.28,66.53 ; SS6.1 98.06,63.75 ; 7.41,38.15 J20.A20 ; J20.A20 8.87,38.15 ; J20.A20 8.14,38.88 ; J20.A20 8.14,37.42 ; J12.2 107.18,41.5 ; J12.2 107.88,40.8 ; J12.2 106.47,40.8 ; 5.41,35.15 J20.A23 ; J20.A23 6.14,34.42 ; J20.A23 6.14,35.88 ; J20.A23 6.87,35.15 ; J20.B21 3.64,37.88 ; J20.B21 2.91,37.15 ; J20.B21 3.64,36.42 ; J20.B21 4.37,37.15 ; 7.41,34.15 J20.A24 ; J20.A24 8.87,34.15 ; J20.A24 8.14,33.42 ; J20.A24 8.14,34.88 ; 2.91,53.15 J20.B7 ; J20.B7 3.64,52.42 ; J20.B7 3.64,53.88 ; J20.B7 4.37,53.15 ; J20.B29 4.37,29.15 ; J20.B29 3.64,29.88 ; J20.B29 3.64,28.42 ; J20.B29 2.91,29.15 ; 0.91,32.15 J20.B26 ; J20.B26 1.64,31.42 ; J20.B26 1.64,32.88 ; J20.B26 2.37,32.15 ; 1.64,39.42 J20.B18 ; J20.B18 1.64,40.88 ; J20.B18 2.37,40.15 ; J20.B18 0.91,40.15 ; J18.2 108.46,93.9 ; J18.2 107.31,93.9 ; J18.2 107.89,94.47 ; SW3.3 15.32,10.47 ; SW3.3 16.2,9.59 ; SW3.3 14.44,9.59 ; SW3.3 15.32,8.71 ; SW2.1 20.49,11.54 ; SW2.1 19.61,10.66 ; SW2.1 18.73,11.54 ; SW2.1 19.61,12.42 ; J9.4 119.37,94.11 ; J9.4 120.1,93.38 ; J9.4 119.37,92.65 ; J9.4 118.64,93.38 ; 137.6,87.52 J10.4 ; J10.4 136.62,88.5 ; J10.4 138.58,88.5 ; J10.4 137.6,89.48 ; 8.14,29.42 J20.A28 ; J20.A28 8.14,30.88 ; J20.A28 7.41,30.15 ; J20.A28 8.87,30.15 ; 7.93,10.66 SW4.1 ; SW4.1 8.8,11.54 ; SW4.1 7.05,11.54 ; SW4.1 7.93,12.42 ; SW3.1 14.65,11.54 ; SW3.1 13.77,12.42 ; SW3.1 12.89,11.54 ; SW3.1 13.77,10.66 ; J20.B13 3.64,45.88 ; J20.B13 2.91,45.15 ; J20.B13 4.37,45.15 ; J20.B13 3.64,44.42 ; J20.B32 2.37,26.15 ; J20.B32 0.91,26.15 ; J20.B32 1.64,26.88 ; J20.B32 1.64,25.42 ; 105.1,19.53 J29.4 ; J29.4 105.83,18.8 ; J29.4 106.55,19.53 ; J20.A27 6.14,31.88 ; J20.A27 6.14,30.42 ; J20.A27 5.41,31.15 ; J20.A27 6.87,31.15 ; 112.02,40.37 J26.2 ; J26.2 112.02,41.62 ; J26.2 111.4,41 ; J9.7 123.6,91.88 ; J9.7 122.87,91.15 ; J9.7 122.14,91.88 ; J9.7 122.87,92.61 ; 1.8,14.2 J25.3 ; J25.3 0.82,15.18 ; J25.3 2.78,15.18 ; J25.3 1.8,16.15 ; J9.13 119.37,90.91 ; J9.13 119.37,89.45 ; J9.13 120.1,90.18 ; J9.13 118.64,90.18 ; 122.87,87.95 J9.16 ; J9.16 122.14,88.68 ; J9.16 122.87,89.41 ; J9.16 123.6,88.68 ; 1.64,35.42 J20.B22 ; J20.B22 1.64,36.88 ; J20.B22 2.37,36.15 ; J20.B22 0.91,36.15 ; 21.16,8.71 SW2.3 ; SW2.3 20.28,9.59 ; SW2.3 22.04,9.59 ; SW2.3 21.16,10.47 ; 108.46,90.43 J18.8 107.31,90.43 ; SS9.1 123.38,19.93 ; SS9.1 117.82,19.93 ; SS9.1 120.6,17.16 ; 107.46,92.15 J18.5 106.31,92.15 ; 5.41,27.15 J20.A31 ; J20.A31 6.87,27.15 ; J20.A31 6.14,27.88 ; J20.A31 6.14,26.42 ; 9.48,8.71 SW4.3 ; SW4.3 8.6,9.59 ; SW4.3 9.48,10.47 ; SW4.3 10.35,9.59 ; 5.41,43.15 J20.A15 ; J20.A15 6.87,43.15 ; J20.A15 6.14,43.88 ; J20.A15 6.14,42.42 ; 136.62,91.5 J10.10 ; J10.10 137.6,90.52 ; J10.10 138.58,91.5 ; J10.10 137.6,92.48 ; J20.A12 8.14,46.88 ; J20.A12 7.41,46.15 ; J20.A12 8.14,45.42 ; 106.31,88.69 J18.11 107.46,88.69 ; 2.91,33.15 J20.B25 ; J20.B25 4.37,33.15 ; J20.B25 3.64,33.88 ; J20.B25 3.64,32.42 ; 106.31,85.22 J18.17 107.46,85.22
  ART04 w0.508: v1(167.19,102.22) v1(163.38,102.22) v1(159.57,102.22) v1(151.95,102.22) v1(148.14,102.22) v1(146.33,102.22) v1(145.33,102.22) v1(144.33,102.22) v1(143.33,102.22) v1(135.9,102.22) v1(134.9,102.22) v1(133.9,102.22) v1(132.9,102.22) v1(129.09,102.22) ; v1(41.46,102.22) v1(42.46,102.22) v1(43.46,102.22) v1(44.46,102.22) v1(45.46,102.22) v1(46.46,102.22) v1(47.46,102.22) v1(48.46,102.22) v1(49.46,102.22) v1(50.46,102.22) v1(51.46,102.22) v1(52.46,102.22) v1(53.46,102.22) v1(54.46,102.22) v1(55.46,102.22) v1(56.46,102.22) v1(57.46,102.22) v1(58.46,102.22) v1(59.46,102.22) v1(60.46,102.22) v1(61.46,102.22) v1(62.46,102.22) v1(63.46,102.22) v1(64.46,102.22) v1(65.46,102.22) v1(66.46,102.22) v1(67.46,102.22) v1(68.46,102.22) v1(69.46,102.22) v1(70.46,102.22) v1(71.46,102.22) v1(72.46,102.22) v1(73.46,102.22) v1(74.46,102.22) v1(75.46,102.22) v1(76.46,102.22) v1(77.46,102.22) v1(78.46,102.22) v1(79.56,102.22) v1(81.18,102.22) v1(82.18,102.22) v1(83.18,102.22) v1(84.18,102.22) v1(85.18,102.22) v1(86.18,102.22) v1(87.18,102.22) v1(90.99,102.22) v1(91.8,102.22) v1(92.8,102.22) v1(93.8,102.22) v1(94.8,102.22) v1(95.8,102.22) v1(96.8,102.22) v1(98.61,102.22) v1(102.42,102.22) v1(106.23,102.22) v1(109.04,102.22) v1(110.04,102.22) v1(111.85,102.22) v1(112.85,102.22) v1(113.85,102.22) v1(117.66,102.22)
  PWR05 w0.254: v1(9.7,42.37) 9.29,42.37 ; v1(9.69,63.41) 9.09,63.41 ; v1(9.69,62.41) 9.09,62.41 ; v1(19.81,63.45) 20.26,63.45
  PWR05 w0.381: J20.A12 8.87,46.15 ; J20.A12 8.14,45.42 ; J20.A12 7.41,46.15 ; J20.A12 8.14,46.88 ; 15.32,8.71 SW3.3 ; SW3.3 15.32,10.47 ; SW3.3 16.2,9.59 ; SW3.3 14.44,9.59 ; J6.10 66.39,87.75 ; J6.10 65.41,88.73 ; J6.10 64.43,87.75 ; J6.10 65.41,86.77 ; J20.A27 6.14,31.88 ; J20.A27 6.87,31.15 ; J20.A27 6.14,30.42 ; J20.A27 5.41,31.15 ; 96.51,90.43 J17.8 97.66,90.43 ; 111.4,41 J26.2 ; J26.2 112.02,41.62 ; J26.2 112.02,40.37 ; J20.B22 2.37,36.15 ; J20.B22 0.91,36.15 ; J20.B22 1.64,35.42 ; J20.B22 1.64,36.88 ; 1.8,14.2 J25.3 ; J25.3 0.82,15.18 ; J25.3 2.78,15.18 ; J25.3 1.8,16.15 ; 8.14,39.42 J20.A18 ; J20.A18 8.87,40.15 ; J20.A18 8.14,40.88 ; J20.A18 7.41,40.15 ; 62.84,11.04 J38.2 ; J38.2 63.75,10.14 ; J38.2 64.65,11.04 ; J38.2 63.75,11.94 ; J20.A15 6.87,43.15 ; J20.A15 6.14,43.88 ; J20.A15 5.41,43.15 ; J20.A15 6.14,42.42 ; J5.2 12.83,93.67 ; J5.2 11.37,93.67 ; J5.2 12.1,95.15 ; J5.2 12.1,92.19 ; 141.45,11.97 J27.2 ; J27.2 140.37,13.05 ; J27.2 142.52,13.05 ; J27.2 141.45,14.13 ; 84.35,9.02 J39.1 ; J39.1 85.08,9.75 ; J39.1 83.63,9.75 ; J39.1 84.35,10.48 ; 39.75,10.7 J44.2 40.47,9.97 ; 1.64,25.42 J20.B32 ; J20.B32 0.91,26.15 ; J20.B32 1.64,26.88 ; J20.B32 2.37,26.15 ; 7.05,11.54 SW4.1 ; SW4.1 8.8,11.54 ; SW4.1 7.93,10.66 ; SW4.1 7.93,12.42 ; 87.02,9.02 J39.S2 ; J39.S2 85.8,10.25 ; J39.S2 88.25,10.25 ; J39.S2 87.02,11.48 ; J20.A1 6.87,59.15 ; J20.A1 5.41,59.15 ; J20.A1 6.14,58.42 ; J20.A1 6.14,59.88 ; J17.2 97.66,93.9 ; J17.2 96.51,93.9 ; J17.2 97.09,94.47 ; 95.28,66.53 SS6.1 ; SS6.1 98.06,63.75 ; SS6.1 98.06,69.31 ; SS6.1 100.83,66.53 ; 84.71,85.22 J16.17 85.86,85.22 ; J39.S1 75.29,10.25 ; J39.S1 72.84,10.25 ; J39.S1 74.06,9.02 ; J39.S1 74.06,11.48 ; J10.10 138.58,91.5 ; J10.10 137.6,90.52 ; J10.10 136.62,91.5 ; J10.10 137.6,92.48 ; 105.1,19.53 J29.4 ; J29.4 105.83,18.8 ; J29.4 105.83,20.26 ; J29.4 106.55,19.53 ; J20.A20 8.14,38.88 ; J20.A20 8.14,37.42 ; J20.A20 8.87,38.15 ; J20.A20 7.41,38.15 ; SS8.1 98.06,23.31 ; SS8.1 98.06,17.76 ; SS8.1 95.28,20.53 ; SS8.1 100.83,20.53 ; 3.64,32.42 J20.B25 ; J20.B25 4.37,33.15 ; J20.B25 2.91,33.15 ; J20.B25 3.64,33.88 ; J20.B4 2.37,56.15 ; J20.B4 1.64,56.88 ; J20.B4 0.91,56.15 ; J20.B4 1.64,55.42 ; J20.B13 4.37,45.15 ; J20.B13 2.91,45.15 ; J20.B13 3.64,45.88 ; J20.B13 3.64,44.42 ; 118.64,90.18 J9.13 ; J9.13 120.1,90.18 ; J9.13 119.37,90.91 ; J9.13 119.37,89.45 ; 20.28,9.59 SW2.3 ; SW2.3 21.16,8.71 ; SW2.3 21.16,10.47 ; SW2.3 22.04,9.59 ; 86.86,90.43 J16.8 85.71,90.43 ; 2.91,29.15 J20.B29 ; J20.B29 4.37,29.15 ; J20.B29 3.64,28.42 ; J20.B29 3.64,29.88 ; 95.51,88.69 J17.11 96.66,88.69 ; 128.94,13.05 J27.5 ; J27.5 130.02,14.13 ; J27.5 130.02,11.97 ; J27.5 131.09,13.05 ; SS12.1 132.83,40.79 ; SS12.1 130.05,38.01 ; SS12.1 132.83,35.23 ; SS12.1 135.6,38.01 ; 84.71,88.69 J16.11 85.86,88.69 ; 106.31,88.69 J18.11 107.46,88.69 ; J10.4 137.6,89.48 ; J10.4 136.62,88.5 ; J10.4 138.58,88.5 ; J10.4 137.6,87.52 ; 144.8,17.16 SS10.1 ; SS10.1 144.8,22.71 ; SS10.1 142.02,19.93 ; SS10.1 147.58,19.93 ; 8.14,33.42 J20.A24 ; J20.A24 8.14,34.88 ; J20.A24 8.87,34.15 ; J20.A24 7.41,34.15 ; 46.03,87.75 J7.10 ; J7.10 47.01,88.73 ; J7.10 47.99,87.75 ; J7.10 47.01,86.77 ; 95.51,92.15 J17.5 96.66,92.15 ; SS11.1 163.82,10.46 ; SS11.1 158.26,10.46 ; SS11.1 161.04,13.24 ; J38.3 66.29,11.94 ; J38.3 67.19,11.04 ; J38.3 65.38,11.04 ; J38.3 66.29,10.14 ; 106.31,92.15 J18.5 107.46,92.15 ; 85.86,92.15 J16.5 84.71,92.15 ; 80.54,9.02 J39.4 ; J39.4 80.54,10.48 ; J39.4 81.27,9.75 ; J39.4 79.82,9.75 ; J20.B16 1.64,42.88 ; J20.B16 0.91,42.15 ; J20.B16 1.64,41.42 ; J20.B16 2.37,42.15 ; 119.37,92.65 J9.4 ; J9.4 120.1,93.38 ; J9.4 118.64,93.38 ; J9.4 119.37,94.11 ; 107.18,40.09 J12.2 ; J12.2 107.88,40.8 ; J12.2 107.18,41.5 ; J12.2 106.47,40.8 ; J39.7 77.46,9.75 ; J39.7 76.73,10.48 ; J39.7 76.73,9.02 ; J39.7 76.01,9.75 ; J18.2 107.89,94.47 ; J18.2 107.31,93.9 ; J18.2 108.46,93.9 ; 95.51,85.22 J17.17 96.66,85.22 ; 3.64,36.42 J20.B21 ; J20.B21 3.64,37.88 ; J20.B21 2.91,37.15 ; J20.B21 4.37,37.15 ; J16.2 86.86,93.9 ; J16.2 85.71,93.9 ; J16.2 86.29,94.47 ; 29.28,20.53 SS7.1 ; SS7.1 32.06,23.31 ; SS7.1 34.83,20.53 ; SS7.1 32.06,17.76 ; SW1.3 27.88,9.59 ; SW1.3 27,10.47 ; SW1.3 27,8.71 ; SW1.3 26.13,9.59 ; 122.87,87.95 J9.16 ; J9.16 122.14,88.68 ; J9.16 122.87,89.41 ; J9.16 123.6,88.68 ; 8.14,29.42 J20.A28 ; J20.A28 7.41,30.15 ; J20.A28 8.14,30.88 ; J20.A28 8.87,30.15 ; J41.5 47.49,11.43 ; J41.5 48.22,10.7 ; J41.5 47.49,9.97 ; J41.5 46.76,10.7 ; 113.25,24.77 J28.4 ; J28.4 113.25,26.22 ; J28.4 112.52,25.49 ; J28.4 113.98,25.49 ; SS9.1 123.38,19.93 ; SS9.1 117.82,19.93 ; SS9.1 120.6,22.71 ; SS9.1 120.6,17.16 ; J20.A23 6.14,35.88 ; J20.A23 6.14,34.42 ; J20.A23 5.41,35.15 ; J20.A23 6.87,35.15 ; 36.47,9.97 J44.4 ; J44.4 37.2,10.7 ; J44.4 35.75,10.7 ; SW4.3 10.35,9.59 ; SW4.3 8.6,9.59 ; SW4.3 9.48,8.71 ; SW4.3 9.48,10.47 ; 107.46,85.22 J18.17 106.31,85.22 ; 0.91,32.15 J20.B26 ; J20.B26 1.64,32.88 ; J20.B26 2.37,32.15 ; J20.B26 1.64,31.42 ; J20.A4 8.14,56.88 ; J20.A4 7.41,56.15 ; J20.A4 8.87,56.15 ; J20.A4 8.14,55.42 ; J20.B18 1.64,40.88 ; J20.B18 1.64,39.42 ; J20.B18 0.91,40.15 ; J20.B18 2.37,40.15 ; 16.67,93.67 J5.3 ; J5.3 18.13,93.67 ; J5.3 17.4,92.19 ; J5.3 17.4,95.15 ; J44.6 33.2,10.7 ; J44.6 32.47,9.97 ; J44.6 31.75,10.7 ; 122.14,91.88 J9.7 ; J9.7 122.87,91.15 ; J9.7 123.6,91.88 ; J9.7 122.87,92.61 ; 2.91,53.15 J20.B7 ; J20.B7 4.37,53.15 ; J20.B7 3.64,53.88 ; J20.B7 3.64,52.42 ; SS5.1 32.06,69.31 ; SS5.1 32.06,63.75 ; SS5.1 29.28,66.53 ; SS5.1 34.83,66.53 ; 107.31,90.43 J18.8 108.46,90.43 ; 6.14,26.42 J20.A31 ; J20.A31 5.41,27.15 ; J20.A31 6.87,27.15 ; J20.A31 6.14,27.88
  BOTTOM w0.254: R171.2 98.3,66.29 SS6.1 ; v1(113.08,75.59) 113.12,75.59 113.28,75.75 Q21.2 ; v1(136.66,98.93) R103.2 v1(137.68,97.92) ; D43.1 115.43,80.64 v1(115.94,81.15) 115.43,81.66 D41.1 ; R295.2 137.45,31.66 v1(137.54,31.75) ; v1(137.79,74.93) C94.2 ; C187.2 v1(125.26,35.58) ; R322.2 19.04,38.42 v1(18.83,38.63) ; v1(35.93,95.76) C289.2 C111.2 ; J36.4 v1(167.11,45.06) ; D28.1 87.12,77.55 v1(87.6,77.06) ; C207.2 v1(150.11,25.92) ; v1(97.96,27.61) Q2.2 99.45,27.16 R135.2 ; 14.02,89.6 R308.2 v1(14.02,90.18) ; J36.21 v1(167.14,36.56) ; v1(19.53,53.12) 19.3,52.89 R274.2 ; R60.2 R59.2 53.34,72.02 v1(53.34,71.01) ; D56.2 v1(6.68,20.94) ; v1(129.92,29.08) 129.79,28.95 C314.2 C313.2 v1(131.19,26.8) ; J37.23 v1(167.11,46.06) ; v2(62.07,17.69) 62.07,25.53 v1(62.23,25.69) 62.14,25.69 57.02,30.8 v1(57.02,55.01) 57.02,56.02 58.02,57.02 v1(58.04,57.02) ; v1(115.82,78.87) 115.31,79.38 D44.1 ; v1(109.83,75.75) Q20.2 ; C209.2 v1(150.11,28.21) ; v1(4.97,71.57) v1(5.97,71.57) J15.7 ; v1(162.36,35.07) C277.2 v1(163.08,35.79) ; 24.25,94.03 v1(24.26,94.02) ; 24.25,94.03 R97.2 ; 24.25,94.03 D12.1 ; J39.7 77.1,10.11 v1(77.1,12.84) D85.1 ; v1(5.59,76.2) 5.72,76.07 J15.16 ; J13.57 v1(128.08,70.11) ; C89.2 R99.2 v1(117.99,98.81) ; v1(167.11,78.35) J33.18 164.5,78.35 ; v1(67.26,31) 66.93,31.33 ; U7.2 v1(121.16,99.95) ; v1(118.98,67.63) Q17.2 ; v1(23.4,98.39) 23.4,97.66 23.65,97.41 D11.1 ; J33.23 v1(167.1,80.85) ; v1(155.68,54.86) 155.69,54.88 R141.2 ; R16.2 C26.2 14.49,27.52 v1(14.59,27.42) ; v1(164.8,33.04) C276.2 v1(164.08,32.32) ; v1(134.98,83.82) 134.34,83.18 134.34,82.8 Q28.2 133.79,81.29 134.3,80.79 v1(134.98,80.79) ; R327.2 34.01,97.04 v1(34.16,97.04) ; J13.39 132.58,72.82 v1(133.3,73.54) ; J13.63 v1(126.58,70.11) ; v1(5.59,77.72) 5.74,77.57 J15.19 ; D13.1 R98.2 v1(20.45,93.47) ; J32.4 v1(167.11,79.85) ; J13.51 v1(129.58,70.11) ; J13.18 v1(137.83,62.37) ; R263.2 150.27,52.85 v1(150.13,52.7) ; C70.2 55.41,73.62 57.4,73.62 v1(57.58,73.8) ; v1(76.95,76.84) 76.57,77.22 R38.2 ; J15.25 v1(5.82,80.57) ; J35.24 166.98,63.96 ; v1(39.12,98.92) R117.1 38.35,98.93 C116.2 ; v1(15.15,71.26) 14.86,71.26 R271.2 ; v2(67.64,67.76) 67.18,68.21 R30.2 ; D24.2 v1(54.62,13.22) ; v1(150.32,70.36) 150.33,70.37 R227.2 ; v1(105.8,72.13) 105.8,71.99 Q11.2 Q12.2 ; v1(16.17,90.19) C87.2 16.17,89.61 ; v1(76.45,83.3) v1(76.45,81.57) C35.2 R43.2 ; R261.2 150.31,54.88 v1(150.13,54.7) ; C166.2 C167.2 v1(109.47,44.98) ; C262.2 10.25,82.19 v1(10.13,82.07) ; C272.2 v1(164.08,49.7) ; R289.2 145.58,32.04 v1(145.29,31.75) ; v1(35.69,102.11) 35.05,101.47 L12.2 ; C243.2 v1(138.81,29.08) ; R58.2 48.26,68.42 48.47,68.21 v2(48.47,67.76) ; R139.2 155.74,52.85 v1(155.68,52.91) ; SS6.1 96.35,68.23 Q10.2 ; SS6.1 99.28,67.75 Q13.2 ; C212.2 C213.2 v1(139.18,46.98) ; D48.2 v1(48.52,13.22) ; v1(21.69,88.14) 20.92,88.91 C77.2 ; C246.2 v1(137.45,18.38) ; D35.1 100.83,79.52 v1(100.88,79.57) ; C97.2 v1(146.99,100.71) ; v1(96.41,79.57) 96.46,79.52 D36.1 ; J13.33 v1(134.08,70.11) ; D31.1 v1(83.69,77.72) ; v1(123.06,26.8) C216.2 C217.2 ; C286.2 C285.2 124.46,97.91 U48.2 v1(124.46,99.95) ; C125.2 v1(1.91,91.38) ; v2(46.87,66.92) 46.87,66.68 49.15,64.4 v2(49.67,64.4) 49.67,63.14 50.7,62.12 v1(50.7,50.81) v1(50.7,48.25) 50.7,47.61 51,47.31 51.97,47.31 52.32,46.95 v1(52.32,44.52) v1(52.32,28.46) 58.07,22.71 58.07,17.89 58.09,17.87 58.09,17.52 58.07,17.49 58.07,17.25 v2(57.67,16.85) ; R192.2 v1(123,75.76) ; D87.1 81.16,12.85 v1(81.15,12.84) 80.9,12.59 80.9,10.11 J39.4 80.13,10.16 v1(80.13,12.84) D86.1 ; v1(60.44,76.84) 60.06,77.22 R68.2 ; C91.2 v1(120.66,95.83) ; C71.2 v1(54.23,71.01) ; v1(20.43,71.26) 20.69,71.52 C124.2 ; J39.1 84.19,9.91 v1(84.19,12.84) D88.1 ; v1(119.96,64.65) R181.2 ; D25.2 v1(52.59,13.22) ; D38.1 94.2,79.52 v1(94.15,79.57) ; C253.2 v1(130.68,98.93) ; Q8.2 93.43,68.63 v1(92.96,69.1) ; v1(130.9,73.54) 131.08,73.36 J13.45 ; v1(18.43,82.31) 18.31,82.19 C86.2 ; R211.2 130.93,83.05 v1(131.06,83.18) ; R160.2 86.39,68.6 v2(87.24,67.76) 87.51,68.02 Q9.2 ; J13.7 v1(140.58,73.53) ; 6.56,14.34 v1(6.57,14.33) ; v1(25.65,69.76) 25.79,69.9 C299.1 ; v1(16.19,25.82) 17.53,25.82 17.79,26.07 R18.2 ; J34.4 v1(167.11,62.46) ; v1(120.14,85.85) U10.3 U10.8 ; J13.1 142.08,69.98 v1(141.3,69.2) ; v1(72.06,71.01) 72.06,72.27 71.55,72.78 R31.2 R32.2 ; C259.2 v1(14.48,82.19) ; C208.2 v1(150.11,27.07) ; J15.22 v1(5.82,79.07) ; v1(19.94,86.37) 19.94,86.64 C78.2 ; v1(36.58,99.95) R118.2 C121.2 v1(36.58,98.93) ; Q18.2 117.09,64.2 116.59,63.69 v1(116.59,62.42) ; J15.28 v1(5.82,82.07) ; C123.2 19.28,71.52 v1(19.54,71.26) ; D55.2 v1(7.45,16.64) ; C168.2 107.28,47.01 v1(106.86,47.43) ; D29.1 v1(84.84,77.72) ; J13.75 v1(123.58,70.11) ; J37.24 167.2,46.56 ; J35.23 v1(167.1,63.46) ; J35.18 v1(167.11,60.96) ; C93.2 v1(134.81,77.21) ; v1(74.64,44.59) 74.24,44.98 74.24,56.3 74.93,56.99 ; C160.2 152.03,68.24 R222.2 ; J20.B32 0.78,27.01 v1(0.78,61.32) ; v1(19.58,48.4) 19.17,47.99 R250.2 ; C92.2 v1(146.99,99.69) ; Q19.2 v1(120.84,75.75) ; C99.2 v1(136.66,100.2) ; D47.2 v1(50.55,13.22) ; R123.2 v1(42.16,90.94) ; C203.2 C202.2 ; J34.21 v1(164.77,53.96) ; U30.2 v1(153.67,25.92) ; U13.2 v1(141.1,97.89) ; v1(19.07,59.41) 19.07,59.28 19.04,59.25 R7.2 ; R149.2 v1(129.67,98.93) ; J37.18 v1(167.11,43.56) ; Q22.2 v1(118.07,74.29) ; v1(125.73,85.85) U11.3 U11.8 ; C25.2 v1(18.79,30.19) ; J13.69 v1(125.08,70.11) ; C284.2 v1(126.62,98.93) ; v1(130.23,18.42) 130.23,18.28 C245.2 ; R325.2 v1(32.2,90.23) ; C242.2 v1(146.56,29.08)
  BOTTOM w0.305: C244.2 131.1,21.33 v1(131.23,21.2) ; C56.2 v1(62.6,86.22) ; J21.5 v1(159.82,21.5) ; v1(116.04,85.6) D42.1 D45.1 C155.2 v1(116.04,83.56) ; v1(166.99,71.35) J32.21 164.63,71.35 ; v1(121.79,29.08) 121.66,28.95 C217.2
  BOTTOM w0.381: J20.A27 6.87,31.15 ; J20.A27 6.14,30.42 ; J20.A27 6.14,31.88 ; J20.A27 5.41,31.15 ; 0.91,36.15 J20.B22 ; J20.B22 1.64,36.88 ; J20.B22 1.64,35.42 ; J20.A24 8.14,34.88 ; J20.A24 8.87,34.15 ; J20.A24 7.41,34.15 ; J20.A24 8.14,33.42 ; 87.02,9.02 J39.S2 ; J39.S2 87.02,11.48 ; J39.S2 85.8,10.25 ; J39.S2 88.25,10.25 ; 80.54,9.02 J39.4 ; J39.4 79.82,9.75 ; J39.4 80.54,10.48 ; J39.4 81.27,9.75 ; J20.A31 6.87,27.15 ; J20.A31 6.14,27.88 ; J20.A31 6.14,26.42 ; J20.A31 5.41,27.15 ; v1(2.67,85.22) 2.68,85.22 J15.31 ; 0.91,56.15 J20.B4 ; J20.B4 1.64,56.88 ; J20.B4 1.64,55.42 ; SW4.3 9.48,10.47 ; SW4.3 10.35,9.59 ; SW4.3 8.6,9.59 ; SW4.3 9.48,8.71 ; 72.84,10.25 J39.S1 ; J39.S1 75.29,10.25 ; J39.S1 74.06,11.48 ; J39.S1 74.06,9.02 ; J38.2 64.65,11.04 ; J38.2 63.75,11.94 ; J38.2 63.75,10.14 ; J38.2 62.84,11.04 ; J20.B18 1.64,40.88 ; J20.B18 0.91,40.15 ; J20.B18 1.64,39.42 ; 8.14,29.42 J20.A28 ; J20.A28 7.41,30.15 ; J20.A28 8.87,30.15 ; J20.A28 8.14,30.88 ; 8.14,37.42 J20.A20 ; J20.A20 7.41,38.15 ; J20.A20 8.87,38.15 ; 65.38,11.04 J38.3 ; J38.3 66.29,11.94 ; J38.3 66.29,10.14 ; J38.3 67.19,11.04 ; 32.06,23.31 SS7.1 29.28,20.53 ; 1.64,25.42 J20.B32 ; J20.B32 1.64,26.88 ; J20.B32 0.91,26.15 ; 84.35,9.02 J39.1 ; J39.1 83.63,9.75 ; J39.1 84.35,10.48 ; J39.1 85.08,9.75 ; 95.28,20.53 SS8.1 ; SS8.1 98.06,23.31 ; SS8.1 100.83,20.53 ; SS8.1 98.06,17.76 ; 0.91,32.15 J20.B26 ; J20.B26 1.64,31.42 ; J20.B26 1.64,32.88 ; v1(118.36,43.81) 118.35,43.83 C162.2 ; J5.2 12.1,95.15 ; J5.2 12.83,93.67 ; J5.2 11.37,93.67 ; J5.2 12.1,92.19 ; J21.11 171.44,17.2 ; J21.11 170.21,16.52 ; J21.11 171.44,15.84 ; J20.A23 6.14,35.88 ; J20.A23 6.87,35.15 ; J20.A23 5.41,35.15 ; J20.A23 6.14,34.42 ; 7.93,10.66 SW4.1 ; SW4.1 7.05,11.54 ; SW4.1 8.8,11.54 ; SW4.1 7.93,12.42 ; J20.B16 1.64,42.88 ; J20.B16 0.91,42.15 ; J20.B16 1.64,41.42 ; 158.26,10.46 SS11.1 161.04,13.24 ; J39.7 76.73,10.48 ; J39.7 77.46,9.75 ; J39.7 76.73,9.02 ; J39.7 76.01,9.75
  BOTTOM w0.508: v1(10.74,7.78) v1(14.55,7.78) v1(18.36,7.78) v1(22.17,7.78) v1(25.98,7.78) v1(29.79,7.78) v1(33.6,7.78) v1(37.41,7.78) v1(41.22,7.78) v1(45.03,7.78) v1(48.84,7.78) v1(52.65,7.78) v1(56.46,7.78) v1(60.27,7.78) v1(64.08,7.78) v1(67.89,7.78) v1(71.7,7.78) v1(75.51,7.78) v1(79.32,7.78) ; J13.77 122.48,73 123.02,73.54 v1(124.5,73.54) ; J32.26 v1(168.64,81.8) ; J21.8 v1(160.96,29.52) ; v1(83.13,7.78) v1(86.94,7.78) v1(90.75,7.78) v1(94.56,7.78) ; v1(143.1,73.56) 143.18,73.48 J13.76 ; 168.64,63.82 J34.26 J32.25 ; J36.25 168.64,35.27 ; 168.64,46.16 J36.26 J34.25 ; J21.9 v1(162.29,16.52) ; J15.32 v1(4.31,64.02)
  BOTTOM w0.762: R39.2 70.65,100.13 ; R39.2 R40.2 ; R39.2 70.65,94.27 R42.2 70.23,93.6 C36.2 72.22,93.76 R40.2 ; R40.2 72.22,100.08 ; 53.51,100.61 R66.2 53.72,98.72 C57.2 51.69,93.47 R71.2
  vias: v1(2.41,81.93) v1(2.41,80.66) v1(2.41,79.01) v1(2.67,77.23) v1(4.23,21.01) v1(4.97,70.57) v1(5.28,65.06) v1(5.31,64.02) v1(6.68,94.19) v1(6.68,93.19) v1(6.68,92.19) v1(6.93,8.78) v1(8.99,18.43) v1(9.68,85.99) v1(9.68,85.19) v1(10.13,80.07) v1(10.13,79.07) v1(10.13,78.07) v1(10.13,77.07) v1(10.68,85.99) v1(10.69,63.41) v1(10.69,62.41) v1(11.13,80.07) v1(11.13,77.07) v1(11.13,76.07) v1(11.32,34.72) v1(11.32,33.72) v1(11.32,32.72) v1(11.34,28.2) v1(11.58,55.12) v1(11.58,49.4) v1(11.58,48.4) v1(11.58,47.4) v1(11.69,60.41) v1(11.69,59.41) v1(12.13,77.07) v1(12.13,76.07) v1(12.32,33.72) v1(12.58,55.12) v1(12.58,49.4) v1(13.2,60.41) v1(13.32,38.48) v1(13.32,33.72) v1(13.34,28.2) v1(13.58,56.12) v1(13.58,55.12) v1(13.58,49.4) v1(13.58,44.51) v1(13.58,43.43) v1(13.58,42.43) v1(14.05,99.88) v1(14.05,98.88) v1(14.02,92.18) v1(14.02,91.18) v1(14.2,60.41) v1(14.32,34.72) v1(14.32,33.72) v1(14.45,38.48) v1(14.58,56.12) v1(14.58,55.12) v1(14.58,49.4) v1(14.58,44.51) v1(14.58,43.43) v1(14.58,42.43) v1(14.59,26.62) v1(14.59,25.82) v1(14.59,25.02) v1(15.15,73.26) v1(15.15,72.26) v1(15.2,60.41) v1(15.32,38.48) v1(15.32,34.72) v1(15.39,27.42) v1(15.39,26.62) v1(15.39,25.82) v1(15.39,25.02) v1(15.65,99.88) v1(15.65,98.88) v1(15.58,48.4) v1(15.81,63.45) v1(16.13,80.07) v1(16.13,79.07) v1(16.13,78.07) v1(16.15,75.26) v1(16.15,74.26) v1(16.15,73.26) v1(16.15,72.26) v1(16.15,71.26) v1(16.15,70.26) v1(16.17,91.19) v1(16.2,60.41) v1(16.19,25.02) v1(16.28,32.6) v1(16.28,31.8) v1(16.58,48.4) v1(16.81,63.45) v1(17.13,80.07) v1(17.13,79.07) v1(17.17,91.19) v1(17.17,90.19) v1(17.2,60.41) v1(17.2,59.41) v1(17.28,32.6) v1(17.53,54.12) v1(17.58,48.4) v1(17.65,72.26) v1(17.83,38.63) v1(18.2,60.41) v1(18.2,59.41) v1(18.53,55.12) v1(18.53,54.12) v1(18.58,48.4) v1(18.58,47.4) v1(18.81,63.45) v1(19.07,60.41) v1(19.54,72.26) v1(19.53,55.12) v1(19.53,54.12) v1(19.58,49.4) v1(19.66,23.7) v1(19.66,22.7) v1(19.66,21.7) v1(19.66,19.7) v1(20.2,60.41) v1(20.32,74.82) v1(20.53,55.12) v1(20.53,54.12) v1(20.53,53.12) v1(20.58,49.4) v1(20.58,48.4) v1(20.66,23.7) v1(20.66,22.7) v1(20.66,21.7) v1(20.66,20.7) v1(20.66,19.7) v1(21.2,60.41) v1(21.53,55.12) v1(21.53,54.12) v1(21.66,23.7) v1(21.66,22.7) v1(21.66,21.7) v1(21.66,20.7) v1(21.66,19.7) v1(22.21,95.38) v1(22.2,60.41) v1(22.66,98.88) v1(22.97,86.37) v1(23.2,60.41) v1(23.4,99.19) v1(24.2,60.41) v1(25.21,63.72) v1(25.2,60.41) v1(25.3,90.26) v1(25.29,75.45) v1(25.7,99.99) v1(25.83,83.48) v1(26.21,63.72) v1(26.2,60.41) v1(26.29,74.45) v1(26.62,90.21) v1(26.56,53.42) v1(26.56,47.68) v1(26.56,46.68) v1(26.56,45.81) v1(26.56,41.81) v1(26.56,37.81) v1(26.56,36.81) v1(27.2,60.41) v1(27.2,59.15) v1(27.28,89.6) v1(27.29,75.45) v1(27.29,74.45) v1(27.53,22.32) v1(27.53,21.32) v1(27.56,53.42) v1(27.56,47.68) v1(27.56,41.81) v1(27.56,37.81) v1(27.58,19.7) v1(27.58,18.7) v1(27.94,85.36) v1(28.2,60.41) v1(28.2,59.15) v1(28.53,22.32) v1(28.53,21.32) v1(28.56,52.42) v1(28.56,47.68) v1(28.56,46.68) v1(28.56,45.81) v1(28.56,41.81) v1(28.56,37.81) v1(28.56,36.81) v1(28.58,19.7) v1(28.58,18.7) v1(28.78,98.89) v1(29.06,90.21) v1(29.08,86.5) v1(29.2,63.41) v1(29.2,62.41) v1(29.2,60.41) v1(29.2,59.15) v1(29.2,58.15) v1(29.45,95.94) v1(29.59,98.9) v1(29.56,54.42) v1(29.56,53.42) v1(29.56,52.42) v1(29.56,39.81) v1(29.56,38.81) v1(30,34.12) v1(30,33.12) v1(30,32.12) v1(30,31.12) v1(30,30.12) v1(30.23,86.5) v1(30.68,87.11) v1(30.89,59.17) v1(31,34.12) v1(31,33.12) v1(31,32.12) v1(31,31.12) v1(31,30.12) v1(31.5,88.69) v1(31.57,85.1) v1(32,34.12) v1(32,33.12) v1(32,32.12) v1(32,31.12) v1(32,30.12) v1(32.26,86.5) v1(32.5,88.69) v1(32.46,83.58) v1(32.54,79.42) v1(32.54,78.42) v1(32.54,77.42) v1(32.54,76.42) v1(32.54,75.42) v1(33,34.12) v1(33,33.12) v1(33,32.12) v1(33,31.12) v1(33,30.12) v1(33.5,88.69) v1(34.37,90.16) v1(34.49,60.09) v1(34.49,58.82) v1(34.52,41.95) v1(34.67,86.5) v1(34.67,82.42) v1(34.67,81.42) v1(34.67,79.42) v1(34.67,77.42) v1(34.67,76.42) v1(34.67,75.38) v1(35.09,88.41) v1(35.15,85.1) v1(35.69,101.31) v1(36.09,88.41) v1(36.49,102.11) v1(36.49,101.31) v1(36.58,87.77) v1(37.49,91.97) v1(37.59,76.38) v1(37.59,75.38) v1(37.59,74.38) v1(37.85,90.16) v1(38.23,87.77) v1(38.23,43.3) v1(38.18,41.65) v1(38.59,76.38) v1(38.59,75.38) v1(38.59,74.38) v1(38.63,57.77) v1(38.61,55.77) v1(38.61,54.5) v1(38.68,60.05) v1(38.66,58.89) v1(38.73,53.23) v1(38.73,51.96) v1(38.73,50.69) v1(38.73,49.54) v1(38.73,48.54) v1(38.85,88.41) v1(39.67,49.32) v1(39.67,48.32) v1(39.98,44.72) v1(40.56,90.06) v1(40.61,61.15) v1(40.64,57.78) v1(40.64,56.53) v1(40.64,54.5) v1(40.64,53.23) v1(40.64,51.96) v1(40.64,50.69) v1(40.74,49.27) v1(40.74,48.27) v1(40.85,88.41) v1(41.02,95.98) v1(41.21,64.98) v1(41.4,84.28) v1(41.94,90.03) v1(42.42,98.93) v1(43.38,34.12) v1(43.38,33.12) v1(43.38,32.12) v1(43.46,82.92) v1(43.92,78.4) v1(43.92,76.38) v1(43.92,75.38) v1(43.92,74.38) v1(43.92,73.38) v1(44.32,56) v1(44.3,53.15) v1(44.27,50.66) v1(44.32,49.24) v1(44.3,43.22) v1(44.3,41.29) v1(44.46,82.92) v1(45.2,27.69) v1(46.14,76.38) v1(46.14,75.38) v1(46.14,74.38) v1(46.14,73.38) v1(46.2,28.69) v1(46.2,27.69) v1(46.29,49.26) v1(47.2,28.69) v1(47.2,27.69) v1(47.45,43.3) v1(47.96,53.23) v1(47.98,52.01) v1(48.01,50.71) v1(48.2,28.69) v1(48.2,27.69) v1(48.41,35.24) v1(50.67,57.11) v1(51.06,78.87) v1(51.06,77.87) v1(51.06,76.87) v1(52.06,78.87) v1(52.06,77.87) v1(52.06,76.87) v1(52.35,43.27) v1(52.27,41.26) v1(52.37,50.38) v1(53.06,78.87) v1(53.06,77.87) v1(53.06,76.87) v1(56.95,35.14) v1(57.3,62.45) v1(58.9,59.78) v1(59.19,77.24) v1(60.07,57.93) v1(61.19,83.26) v1(61.26,57.93) v1(61.34,56.02) v1(61.44,76.84) v1(61.92,50.41) v1(62.1,44.46) v1(62.1,41.32) v1(62.44,80.84) v1(62.44,79.84) v1(62.44,78.84) v1(62.44,77.84) v1(62.44,76.84) v1(62.48,59.02) v1(62.48,56.02) v1(62.6,87.22) v1(62.6,85.22) v1(62.92,50.41) v1(63.75,62.5) v1(63.88,59.02) v1(63.92,50.41) v1(63.98,83.23) v1(64.54,81.52) v1(64.52,61.81) v1(64.92,50.41) v1(65.92,50.41) v1(65.98,70.01) v1(66.2,13.61) v1(66.64,43.33) v1(66.92,74.37) v1(66.92,50.41) v1(66.9,34.79) v1(67.03,26.81) v1(67.69,58.94) v1(67.92,50.41) v1(67.97,32.93) v1(68.5,31) v1(68.53,28.77) v1(68.62,13.61) v1(69.24,44.59) v1(69.46,78.87) v1(69.46,77.87) v1(69.46,76.87) v1(69.62,28.79) v1(69.67,30.98) v1(70.15,35.47) v1(70.28,32.68) v1(70.46,78.87) v1(70.46,77.87) v1(70.46,76.87) v1(70.64,44.59) v1(70.79,28.79) v1(70.92,38.75) v1(70.92,37.48) v1(71.46,78.87) v1(71.46,77.87) v1(71.46,76.87) v1(71.45,31.84) v1(71.64,44.59) v1(72.64,44.59) v1(72.64,35.85) v1(72.61,27.98) v1(72.97,32.43) v1(74.35,40.53) v1(74.78,37.51) v1(74.78,35.98) v1(75.64,44.59) v1(76.07,37.1) v1(77.39,38.65) v1(77.64,44.59) v1(77.65,35.96) v1(79.51,76.84) v1(80.01,15) v1(80.33,99.18) v1(80.51,79.84) v1(80.51,78.84) v1(80.51,77.84) v1(80.51,76.84) v1(80.77,48.78) v1(81.79,50.05) v1(82.55,51.32) v1(82.64,41.46) v1(83.67,73.93) v1(84.76,73.93) v1(85.85,75.28) v1(87.73,87.54) v1(87.76,92.71) v1(87.76,91.06) v1(87.76,89.38) v1(88.54,74.08) v1(89.94,41.24) v1(89.99,47.21) v1(90.09,21.88) v1(90.99,47.21) v1(91.06,41.24) v1(91.29,43.17) v1(91.52,21.88) v1(92.58,73.95) v1(94.01,47.46) v1(96.01,81.02) v1(96.11,73.95) v1(96.11,40.86) v1(96.75,43.4) v1(97.41,12.54) v1(98.32,91.11) v1(98.35,89.28) v1(99.19,92.2) v1(99.26,71.31) v1(101.04,46.63) v1(101.04,45.56) v1(101.04,44.6) v1(101.08,48.83) v1(101.07,47.51) v1(101.07,43.53) v1(102.12,40.56) v1(103.12,40.56) v1(103.86,47.43) v1(104.12,42.56) v1(104.12,41.56) v1(104.12,40.56) v1(104.86,47.43) v1(105.84,75.48) v1(105.86,47.43) v1(106.35,12.56) v1(106.93,53.99) v1(107.59,73.4) v1(108.08,12.59) v1(108.92,94.99) v1(108.92,92.69) v1(109.04,101.22) v1(109.14,73.09) v1(109.35,90.82) v1(109.35,89.41) v1(109.52,10.48) v1(109.6,78.73) v1(110.04,101.22) v1(110.6,15.13) v1(111.6,15.13) v1(111.66,13.45) v1(111.85,101.22) v1(111.85,100.22) v1(111.85,99.22) v1(112.7,53.08) v1(112.68,16.27) v1(112.76,73.37) v1(112.8,69.89) v1(112.85,99.22) v1(113.68,16.27) v1(113.77,76.95) v1(114,73.32) v1(114.68,16.27) v1(114.83,12.59) v1(115.11,39.65) v1(115.27,59.04) v1(115.84,43.18) v1(117.75,25.39) v1(119.13,13.53) v1(119.66,97.83) v1(119.66,96.83) v1(119.66,95.83) v1(120.32,69.66) v1(120.52,44.97) v1(121.36,49.66) v1(122.01,47.97) v1(122.01,45.97) v1(122.01,44.97) v1(122.26,37.58) v1(122.26,32.58) v1(122.46,99.95) v1(122.58,95.83) v1(122.67,81.34) v1(122.68,12.97) v1(122.78,59.32) v1(123.26,37.58) v1(123.26,32.58) v1(123.46,99.95) v1(123.58,95.83) v1(123.78,59.32) v1(124.26,37.58) v1(124.26,32.58) v1(124.58,95.83) v1(124.78,59.32) v1(125.26,37.58) v1(125.26,36.58) v1(125.26,34.58) v1(125.26,32.58) v1(125.46,99.95) v1(125.91,25.21) v1(126.26,38.58) v1(127.2,34.91) v1(127.26,38.58) v1(127.65,57.21) v1(128.25,81.34) v1(128.26,38.58) v1(128.26,37.58) v1(128.73,43.17) v1(132.36,44.77) v1(134.45,18.38) v1(134.39,14.82) v1(134.87,84.67) v1(135.45,18.38) v1(135.64,14.8) v1(135.74,86.32) v1(136.45,18.38) v1(136.6,84.65) v1(137.54,40.4) v1(137.72,36.7) v1(137.72,35.7) v1(138.41,45.13) v1(138.45,18.38) v1(138.35,14.75) v1(138.54,40.4) v1(138.72,36.7) v1(138.72,35.7) v1(139.01,83.28) v1(139.41,45.13) v1(139.54,40.4) v1(139.72,36.7) v1(139.72,35.7) v1(139.98,58) v1(140.3,81.44) v1(140.3,80.64) v1(140.3,79.84) v1(140.41,47.13) v1(140.41,46.13) v1(140.41,45.13) v1(140.54,40.4) v1(140.74,17.79) v1(140.87,16.07) v1(140.87,14.75) v1(141.1,81.44) v1(141.1,80.64) v1(141.1,79.84) v1(141.9,81.44) v1(141.9,80.64) v1(141.9,79.84) v1(141.87,16.07) v1(141.87,14.75) v1(142.1,97.89) v1(142.8,86.02) v1(142.87,16.07) v1(142.87,14.75) v1(143.1,97.89) v1(143.15,84.71) v1(143.18,83.26) v1(143.8,86.02) v1(144.15,84.71) v1(144.8,86.02) v1(144.82,83.04) v1(144.91,58.32) v1(145.15,84.71) v1(145.52,65.67) v1(145.8,86.02) v1(145.82,83.04) v1(145.91,59.32) v1(145.91,58.32) v1(146.15,84.71) v1(146.8,86.02) v1(146.82,83.04) v1(146.82,78.04) v1(146.94,49.95) v1(147.15,84.71) v1(147.8,86.02) v1(147.82,83.04) v1(147.82,78.04) v1(148.82,83.04) v1(149.57,82.04) v1(149.57,81.04) v1(149.57,80.04) v1(149.63,68.8) v1(149.99,97.55) v1(150.13,56.7) v1(150.13,55.7) v1(150.27,84.62) v1(150.32,72.36) v1(150.32,71.36) v1(151.13,57.7) v1(151.13,56.7) v1(151.13,55.7) v1(151.32,71.36) v1(152.29,91.75) v1(152.29,90.75) v1(153.29,91.75) v1(153.29,90.75) v1(154.05,78.43) v1(154.08,66.46) v1(154.08,65.46) v1(154.08,64.46) v1(154.08,63.46) v1(154.13,51.7) v1(154.13,50.7) v1(154.13,49.7) v1(154.29,91.75) v1(154.29,90.75) v1(154.41,73.5) v1(154.68,57.86) v1(154.68,56.86) v1(154.68,55.86) v1(154.68,54.86) v1(155.05,78.43) v1(155.08,66.46) v1(155.08,65.46) v1(155.08,64.46) v1(155.08,63.46) v1(155.13,51.7) v1(155.13,50.7) v1(155.13,49.7) v1(155.29,90.75) v1(155.5,46.07) v1(155.68,55.86) v1(156.01,68.75) v1(156.11,73.5) v1(156.08,66.46) v1(156.08,65.46) v1(156.08,64.46) v1(156.08,63.46) v1(156.29,91.75) v1(156.29,90.75) v1(156.5,46.07) v1(157.29,91.75) v1(157.29,90.75) v1(157.5,46.07) v1(157.91,88.41) v1(157.99,77.36) v1(158.13,49.7) v1(158.13,48.7) v1(158.8,72.53) v1(159,82.42) v1(159,81.42) v1(159.11,84.22) v1(159.13,74.16) v1(159.13,49.7) v1(159.13,48.7) v1(159.36,70.45) v1(159.66,88.51) v1(159.82,84.72) v1(160.12,78.02) v1(160.13,51.7) v1(160.13,50.7) v1(160.13,49.7) v1(160.53,72.77) v1(160.53,71.5) v1(161.07,70.21) v1(161.09,60.72) v1(161.11,56.66) v1(161.19,88.53) v1(161.26,78.02) v1(162.07,70.21) v1(162.07,52.7) v1(162.07,51.7) v1(162.07,47.39) v1(162.1,39) v1(162.1,37.56) v1(162.2,64.9) v1(162.29,82.3) v1(162.29,81.3) v1(162.28,72.63) v1(162.64,88.48) v1(163.63,78.75) v1(163.77,53.96) v1(164.31,55.08) v1(165.05,88.25) v1(165.08,68.21) v1(165.08,67.21) v1(165.08,66.21) v1(165.08,50.7) v1(165.08,49.7) v1(165.08,48.7) v1(165.79,84.32) v1(166.08,67.21) v1(166.99,69.35) v1(166.99,68.35) v1(167.1,81.85) v1(167.11,59.46) v1(167.11,58.46) v1(167.11,57.46) v1(167.11,56.46) v1(167.11,53.96) v1(167.11,42.06) v1(167.11,41.06) v1(167.11,40.06) v1(167.11,39.06) v1(167.18,28.18) v1(167.18,27.18) v1(167.18,26.18) v1(167.18,25.18) v1(167.18,24.18) v1(167.18,23.18) v1(167.18,22.18) v1(167.18,21.18) v1(167.18,20.18) v1(167.18,19.18) v1(167.18,18.18) v1(167.18,17.18) v1(167.18,16.18) v1(167.18,15.18) v1(168.1,76.85) v1(168.11,63.46) v1(168.11,62.46) v1(168.11,61.46) v1(168.11,60.46) v1(168.11,59.46) v1(168.11,58.46) v1(168.11,57.46) v1(168.11,56.46) v1(168.11,55.46) v1(168.11,53.96) v1(168.11,46.06) v1(168.11,45.06) v1(168.11,44.06) v1(168.11,43.06) v1(168.11,42.06) v1(168.11,41.06) v1(168.11,40.06) v1(168.11,39.06) v1(168.11,38.06) v1(168.11,36.56) v1(168.11,35.56) v1(168.71,75.07) v1(168.94,79.01) v1(169.11,46.06) v1(169.11,45.06) v1(169.11,44.06) v1(169.11,43.06) v1(169.11,42.06) v1(169.11,41.06) v1(169.11,40.06) v1(169.11,39.06) v1(169.11,38.06) v1(169.11,37.06) v1(169.11,36.06) v1(169.16,72.89) v1(169.77,77.61) v1(172.22,96.12) v1(172.22,91.31) v1(172.22,87.5) v1(172.22,83.69) v1(172.22,79.88) v1(172.22,76.07) v1(172.22,72.26) v1(172.22,68.45) v1(172.22,64.64) v1(172.22,60.83) v1(172.22,57.02) v1(172.22,53.21) v1(172.22,49.4) v1(172.22,45.59) v1(172.22,41.78) v1(172.22,37.97) v1(172.22,34.16) v1(172.22,26.54) v1(172.22,22.73) v1(172.22,18.92) v1(172.22,15.11) v2(37.7,14.86) v2(37.7,13.86) v2(39.7,21.86) v2(39.7,20.86) v2(39.7,19.86) v2(40.64,70.04) v2(40.7,21.86) v2(40.7,20.86) v2(40.7,19.86) v2(40.7,17.86) v2(42,19.71) v2(42.07,68.76) v2(42.07,67.76) v2(43.62,17.71) v2(43.67,19.71) v2(44.42,20.51) v2(44.42,19.71) v2(44.42,17.71) v2(50.07,24.25) v2(50.87,24.25) v2(51.03,17.85) v2(54.25,70.2) v2(54.41,15.23) v2(56.67,16.85) v2(61.27,16.85) v2(62.07,24.61) v2(62.07,23.61) v2(63.68,19.78) v2(63.8,23.92) v2(63.78,22.49) v2(63.88,17.03) v2(64.82,23.92) v2(64.9,20.18) v2(64.9,16.93) v2(64.97,22.57) v2(65.41,24.98) v2(66.04,20.18) v2(66.07,21.68) v2(66.4,16.88) v2(66.55,23.81) v2(66.93,28.79) v2(66.98,27.93) v2(69.04,19.96) v2(70.08,16.93) v2(71.98,25.59) v2(72.67,17.67) v2(73.43,25.57) v2(74.42,67.71) v2(75.62,17.67) v2(78.04,66.92) v2(85.06,66.64) v2(88.12,16.85) v2(90.65,16.83) v2(91.44,16.83) v2(126.16,15.31) v2(127.16,15.31) v2(160.73,40.76) v2(160.76,41.8) v2(162.59,43.83) v2(162.59,42.81) v2(162.59,41.8)
